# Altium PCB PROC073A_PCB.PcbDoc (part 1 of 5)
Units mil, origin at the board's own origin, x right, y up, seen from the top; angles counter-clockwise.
Board outline 2165.35 x 2165.35 mil, 6 copper layers (Top Layer, L2, L3, L4, L5, Bottom Layer), stack 55.77 mil thick; 284 components, 233 nets, 945 pads, 1419 vias.
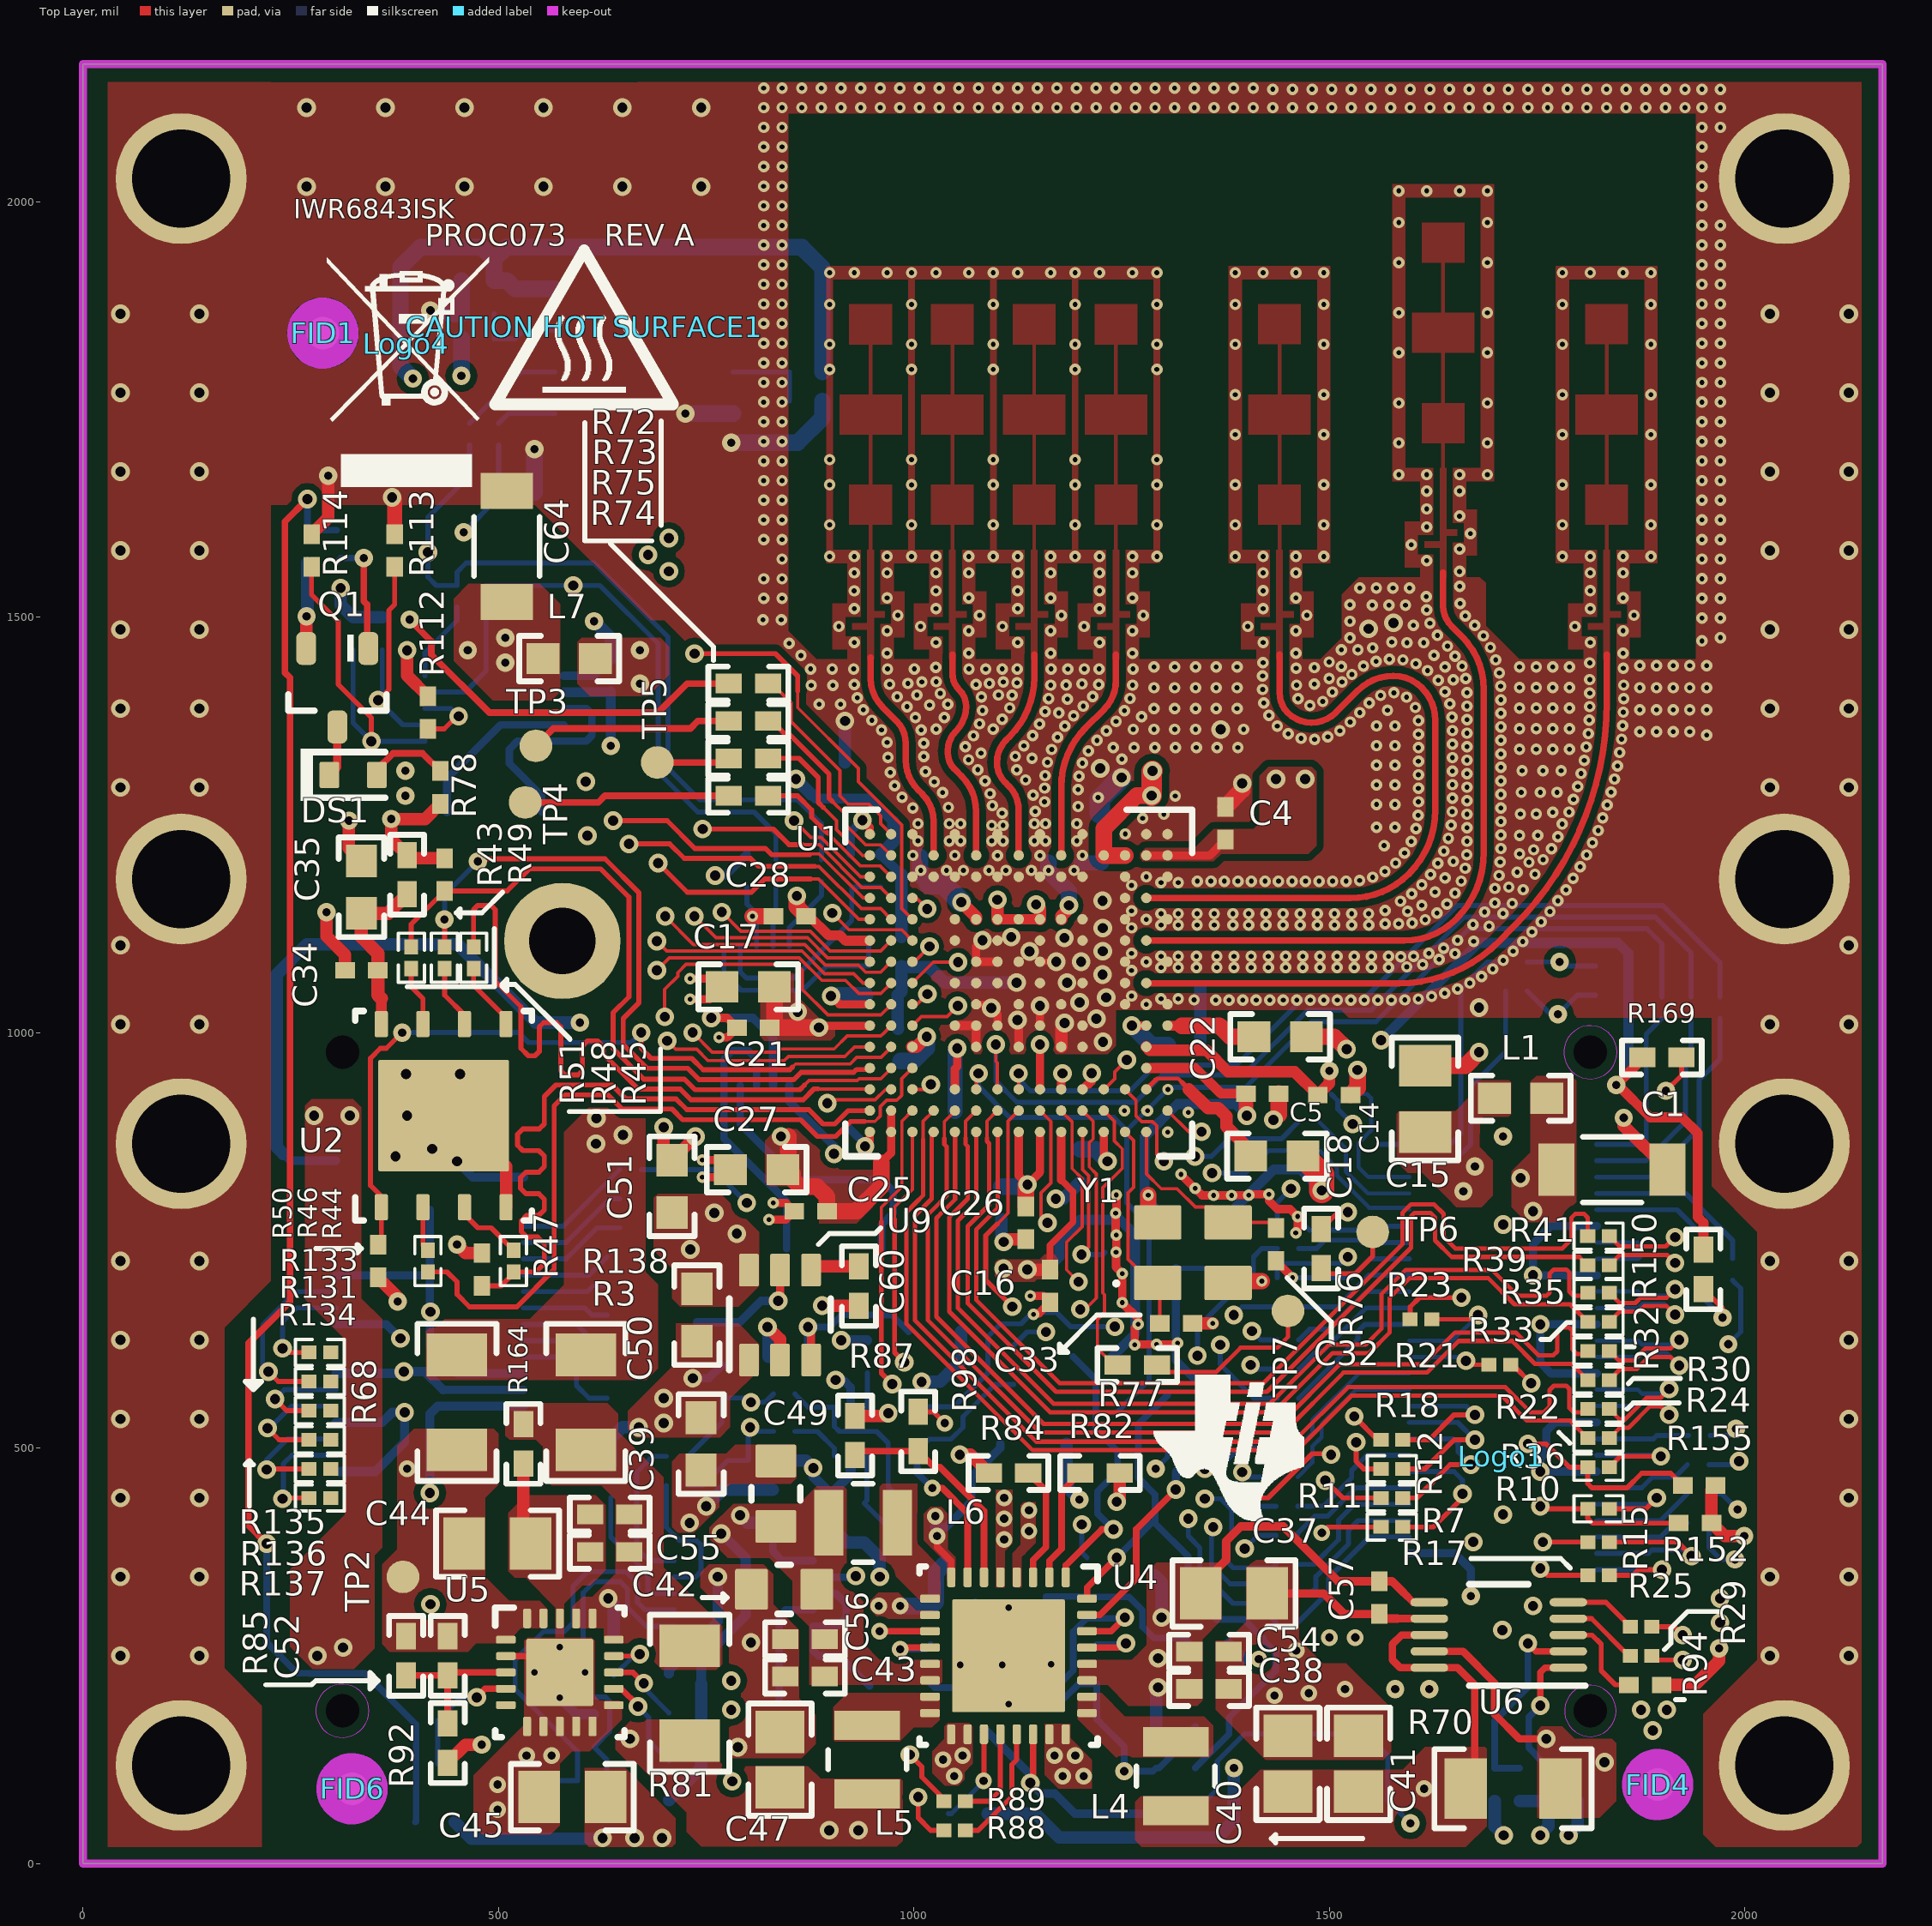
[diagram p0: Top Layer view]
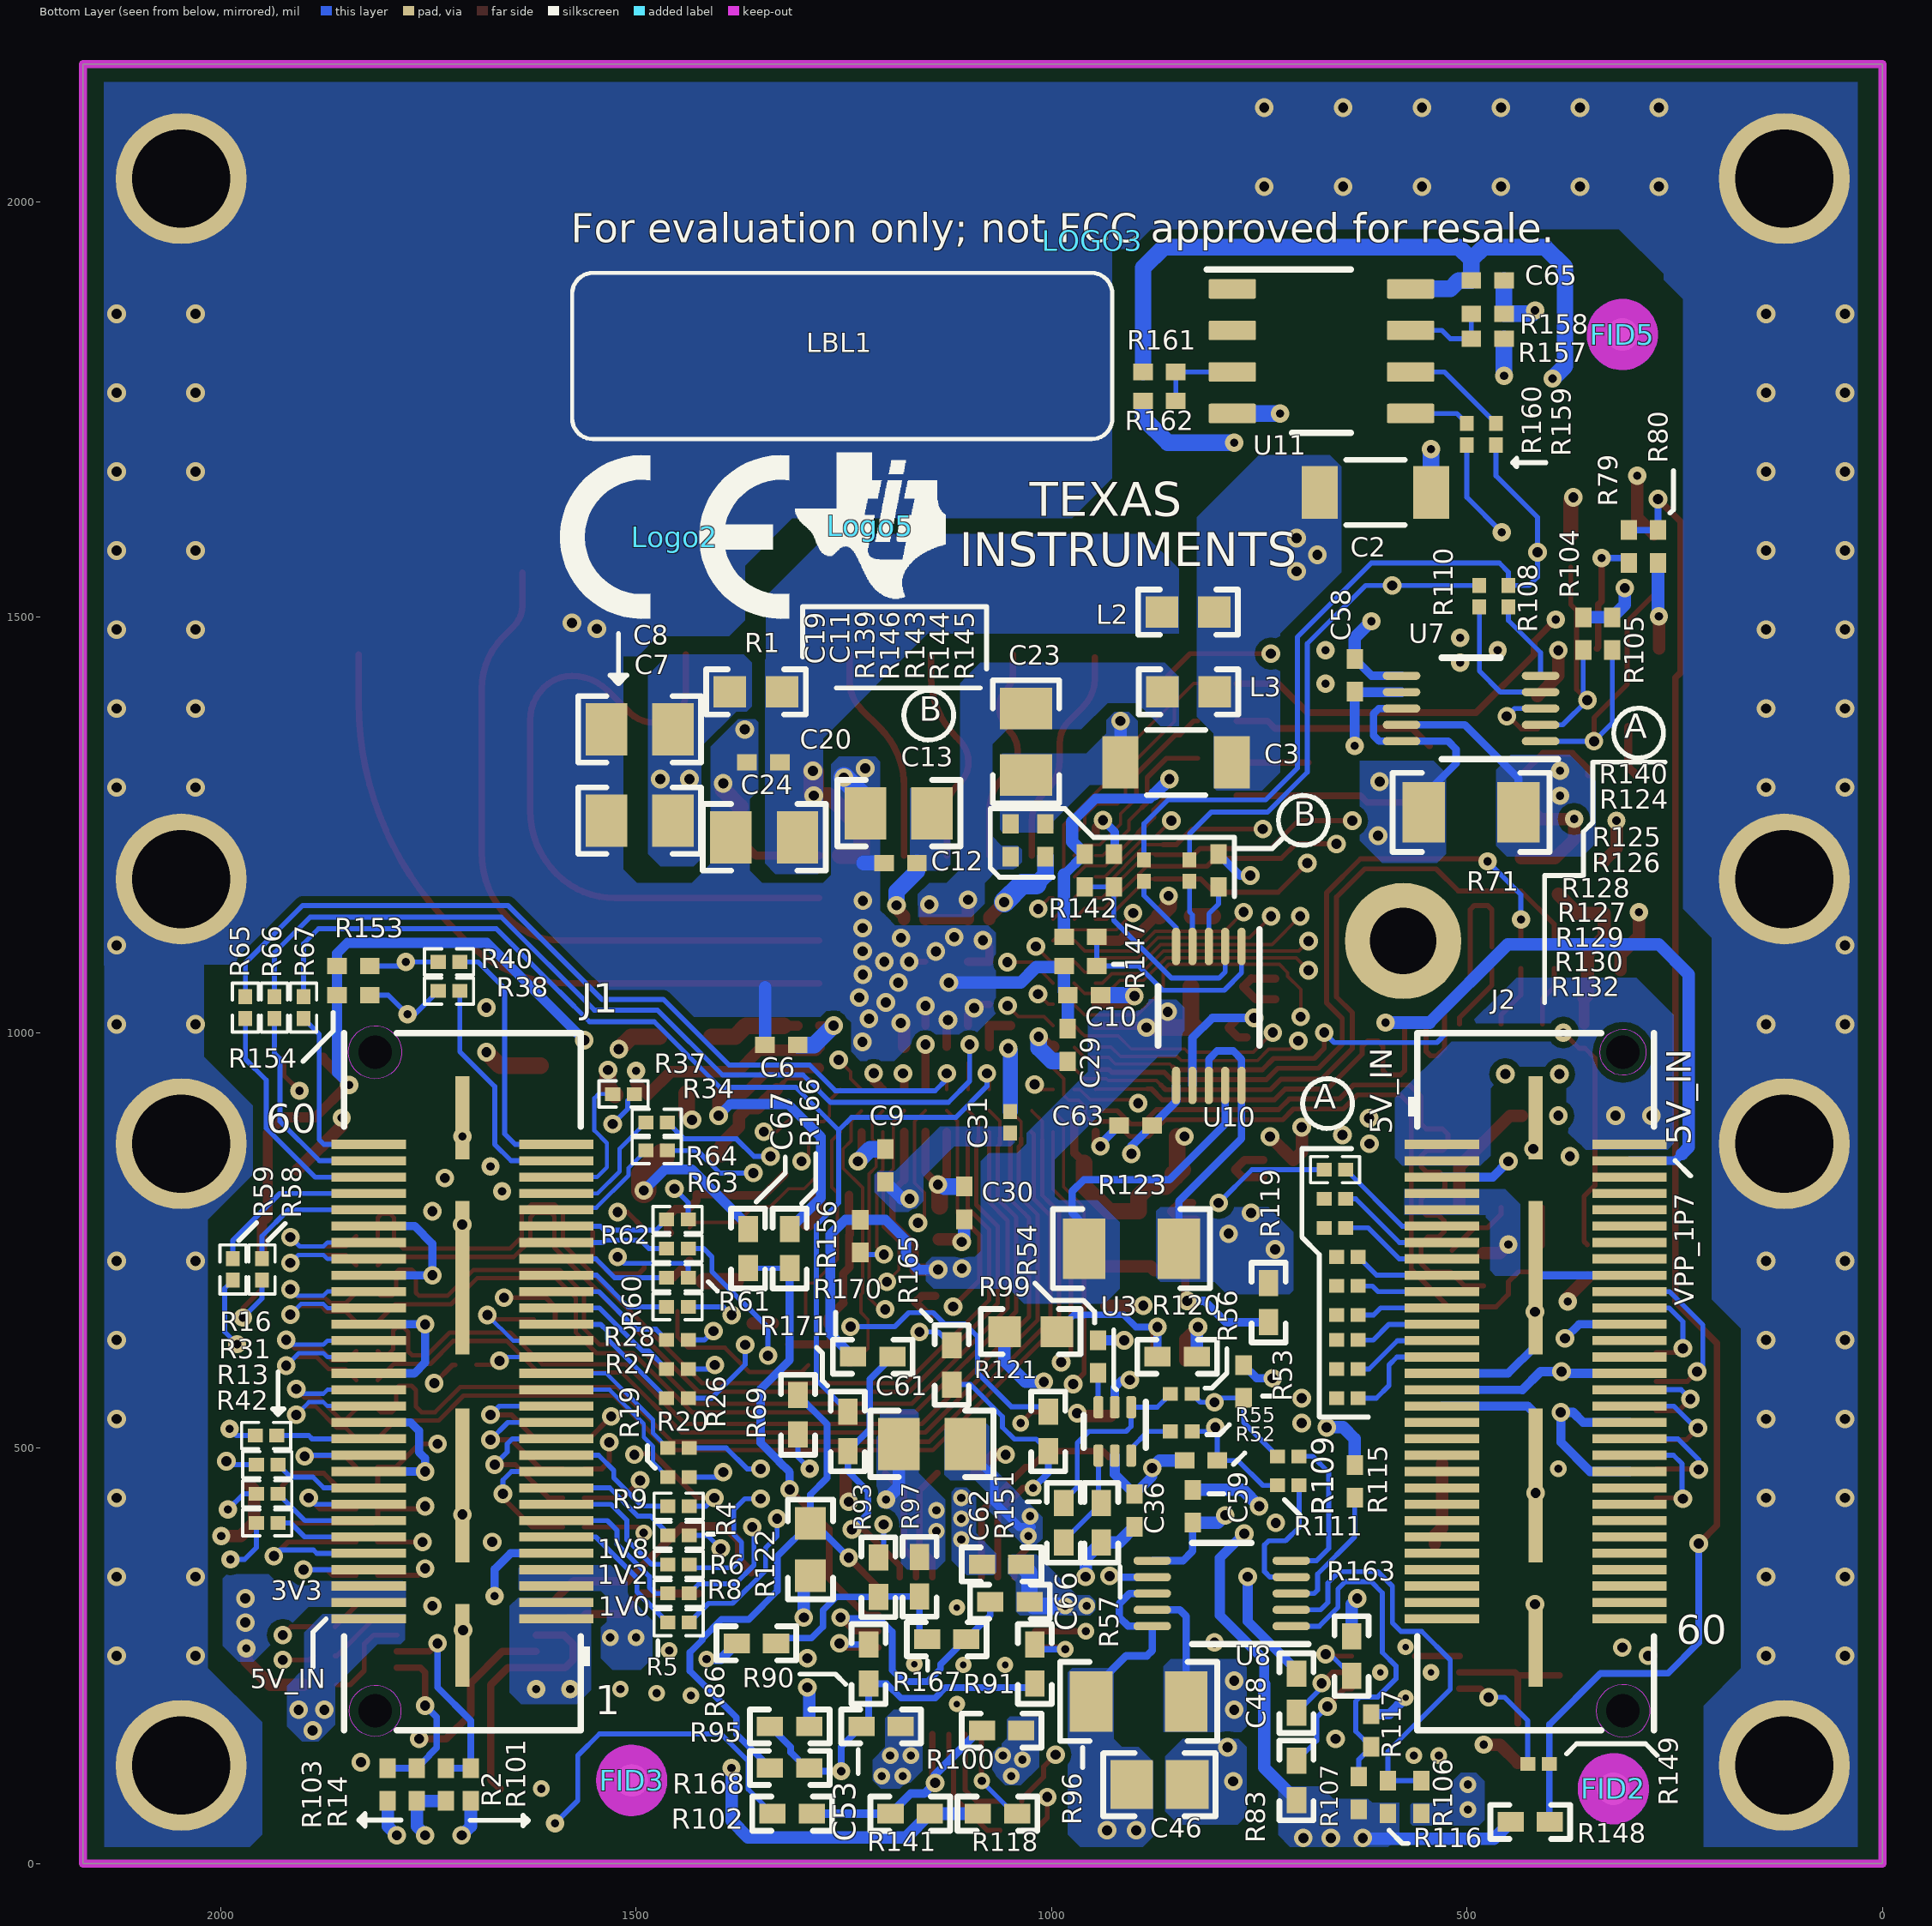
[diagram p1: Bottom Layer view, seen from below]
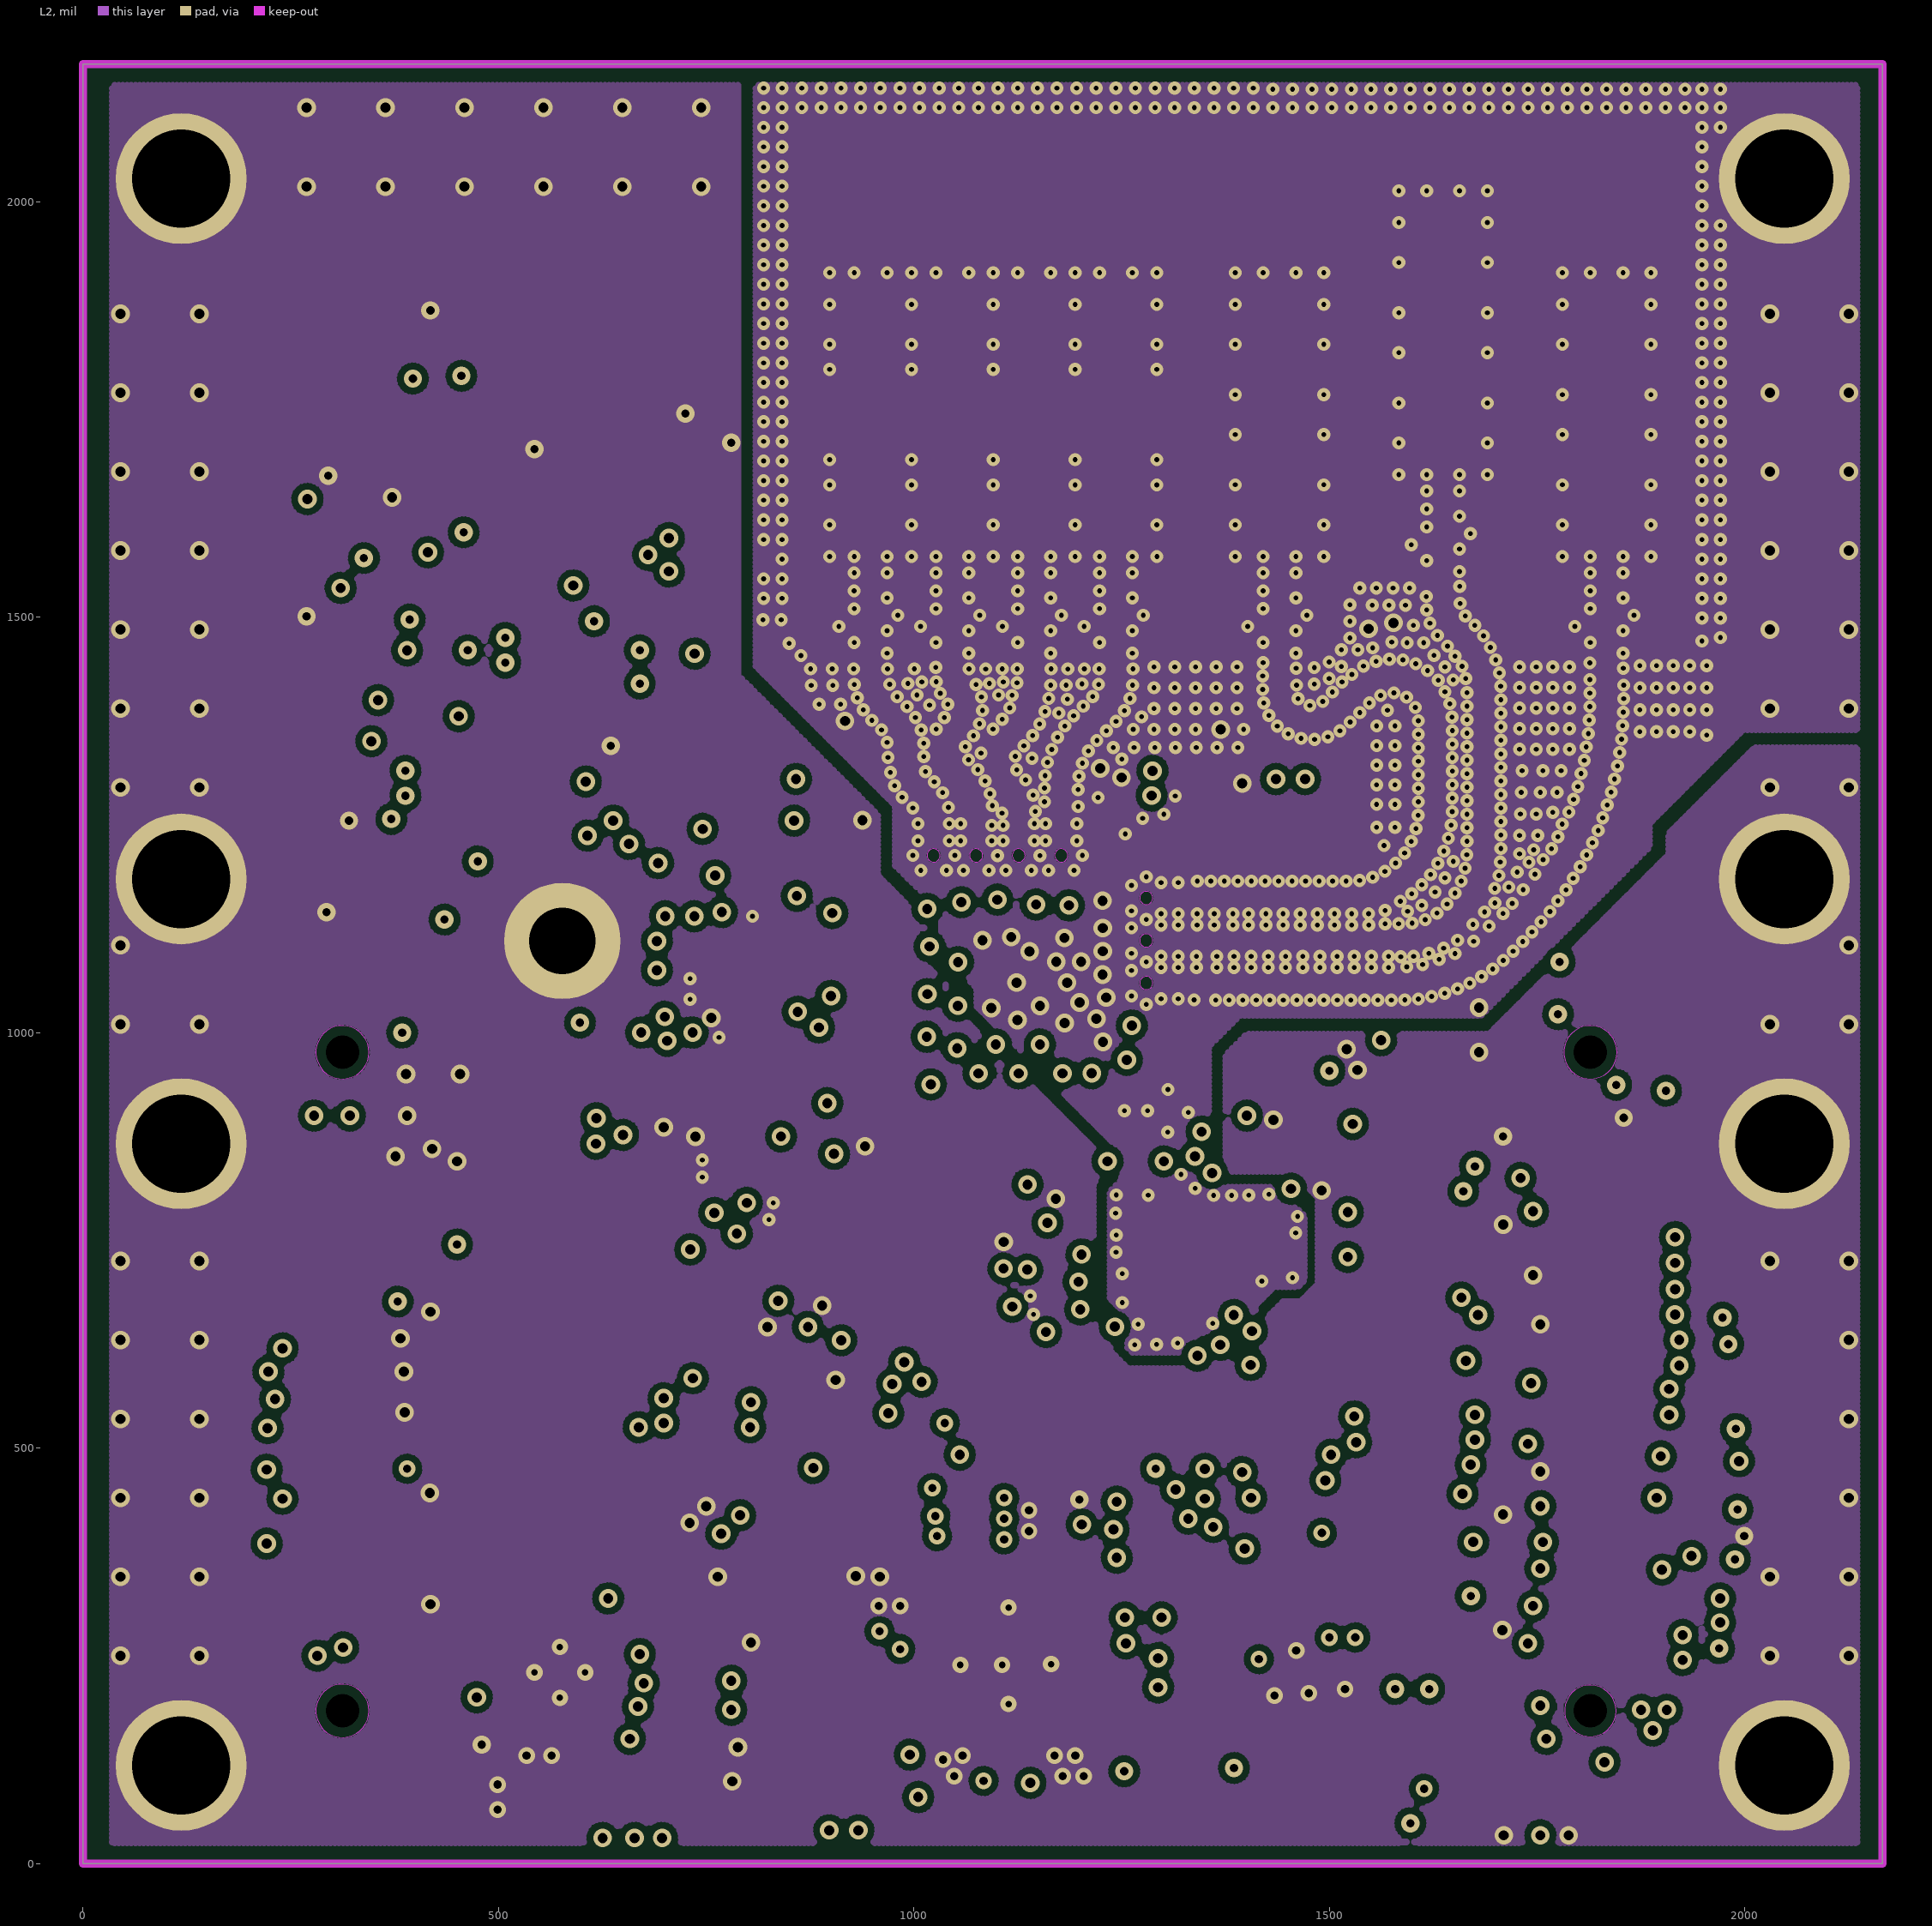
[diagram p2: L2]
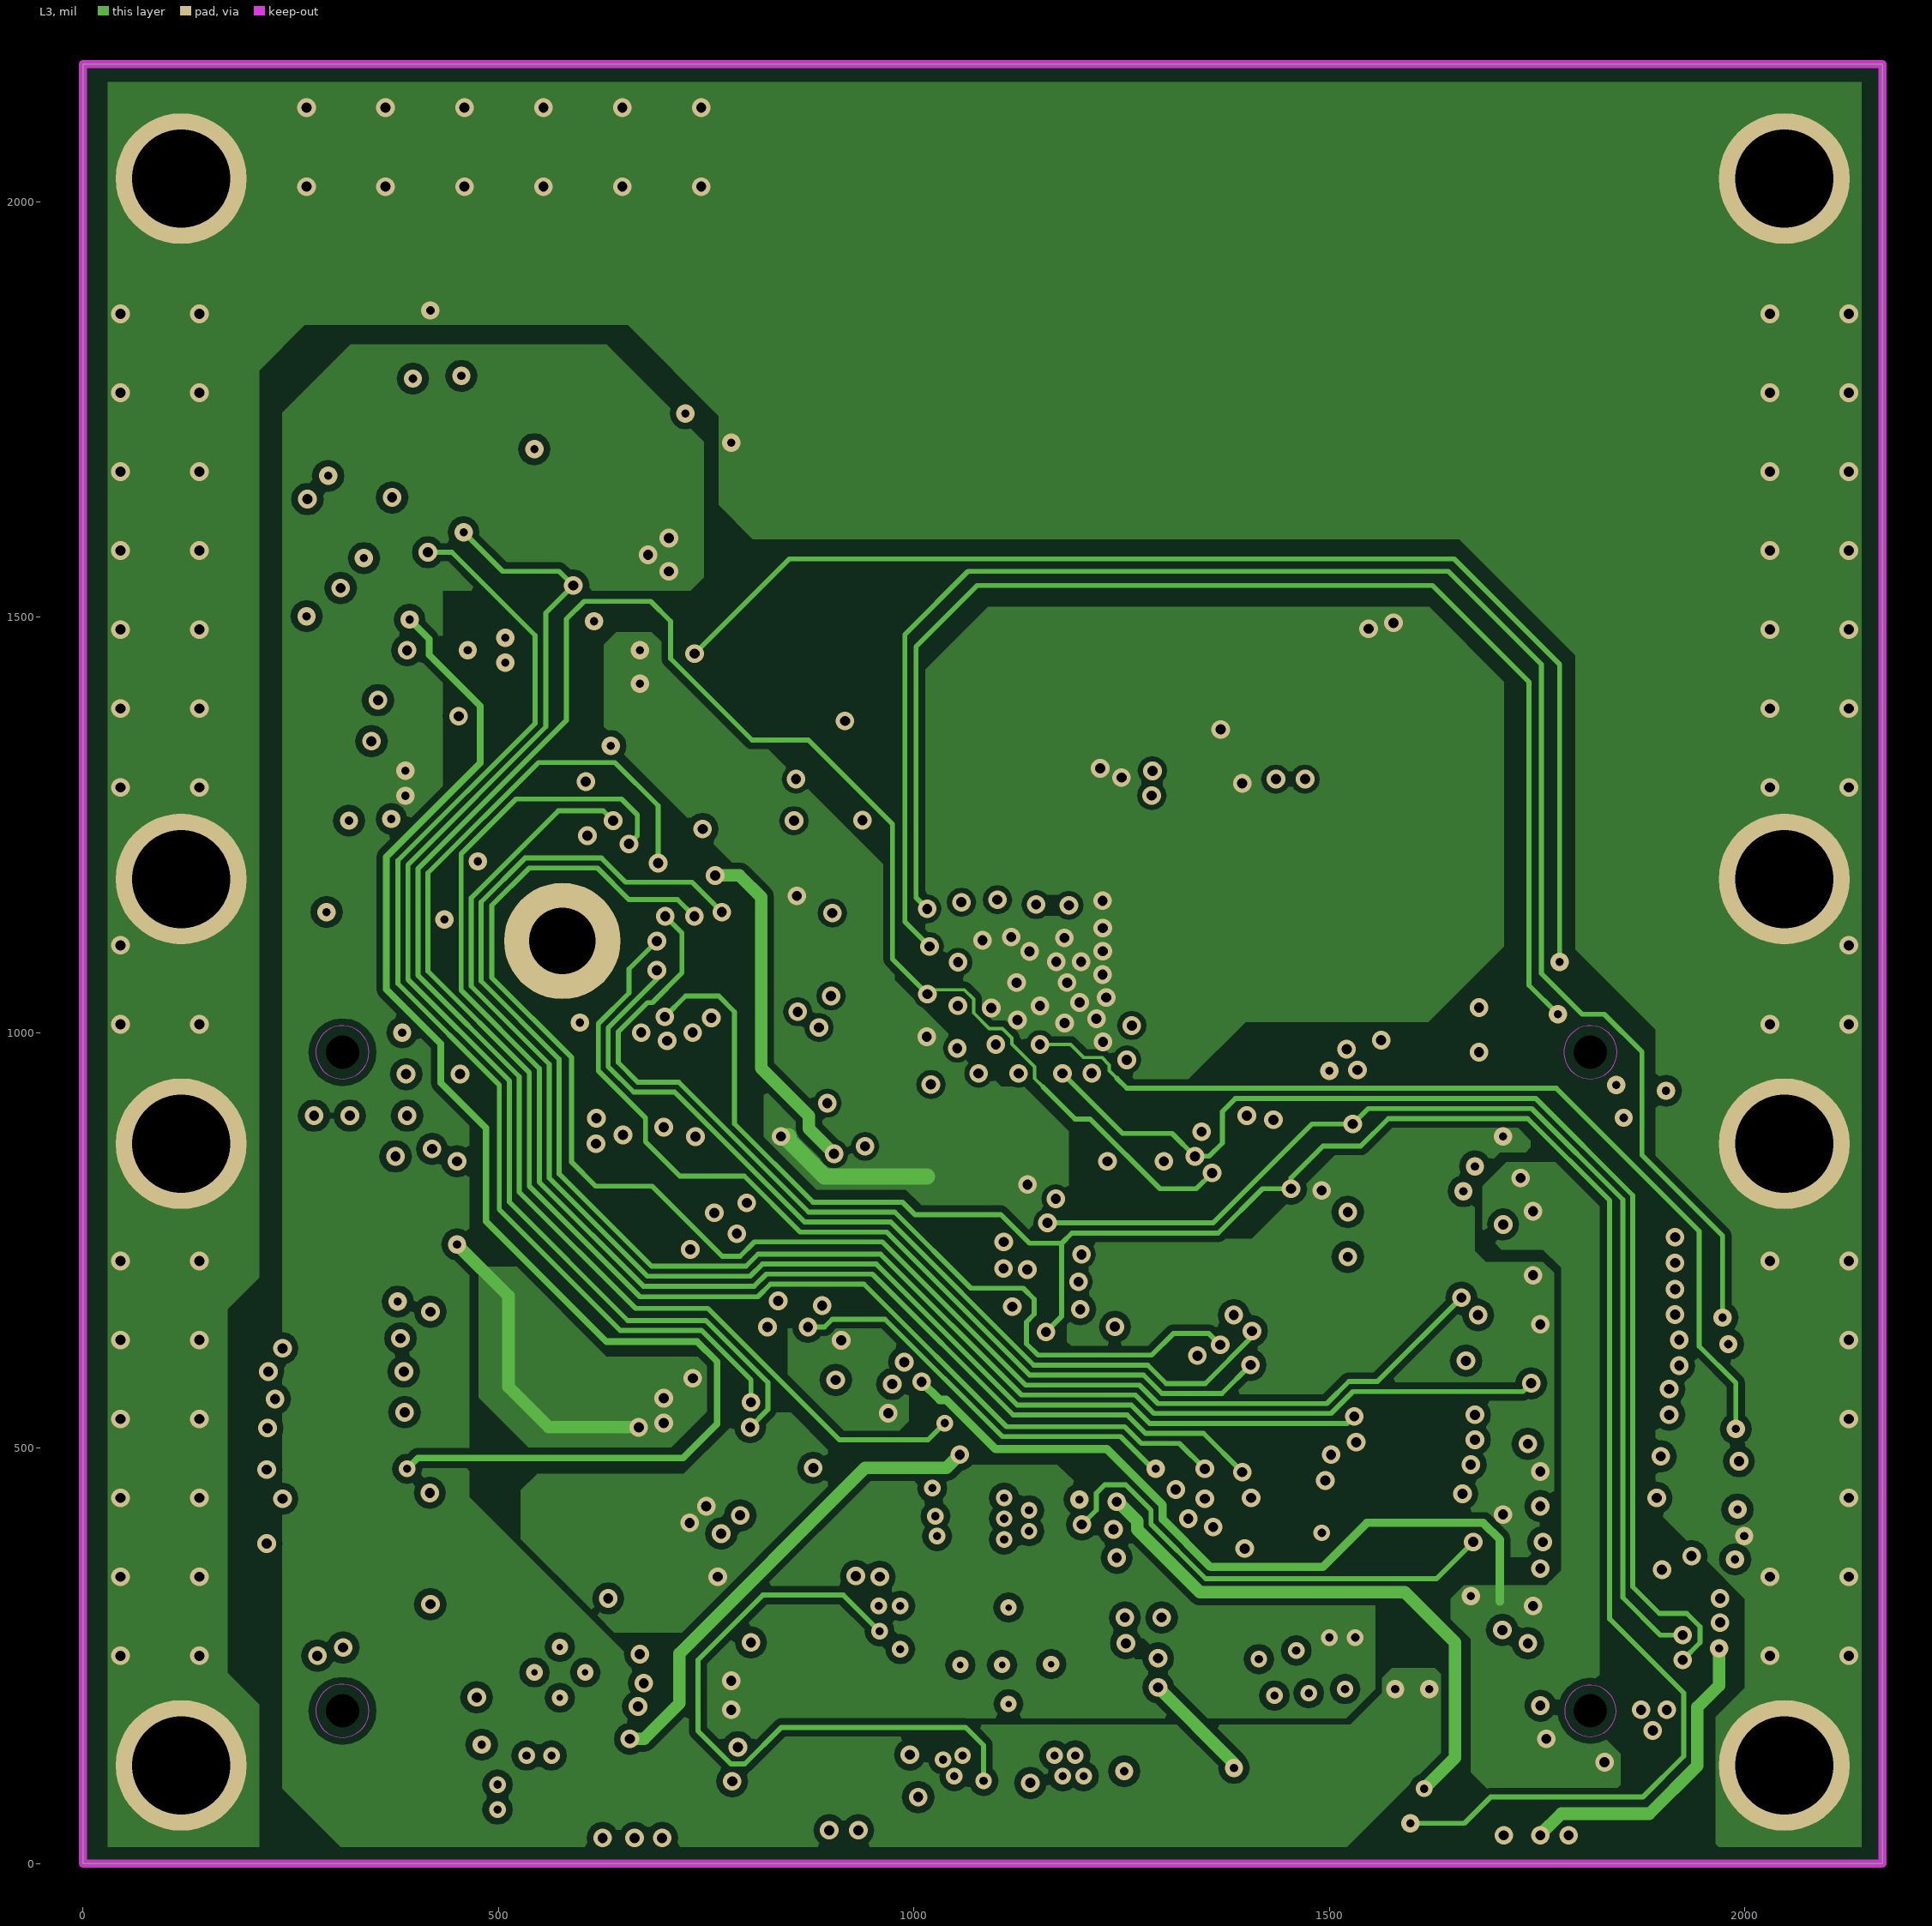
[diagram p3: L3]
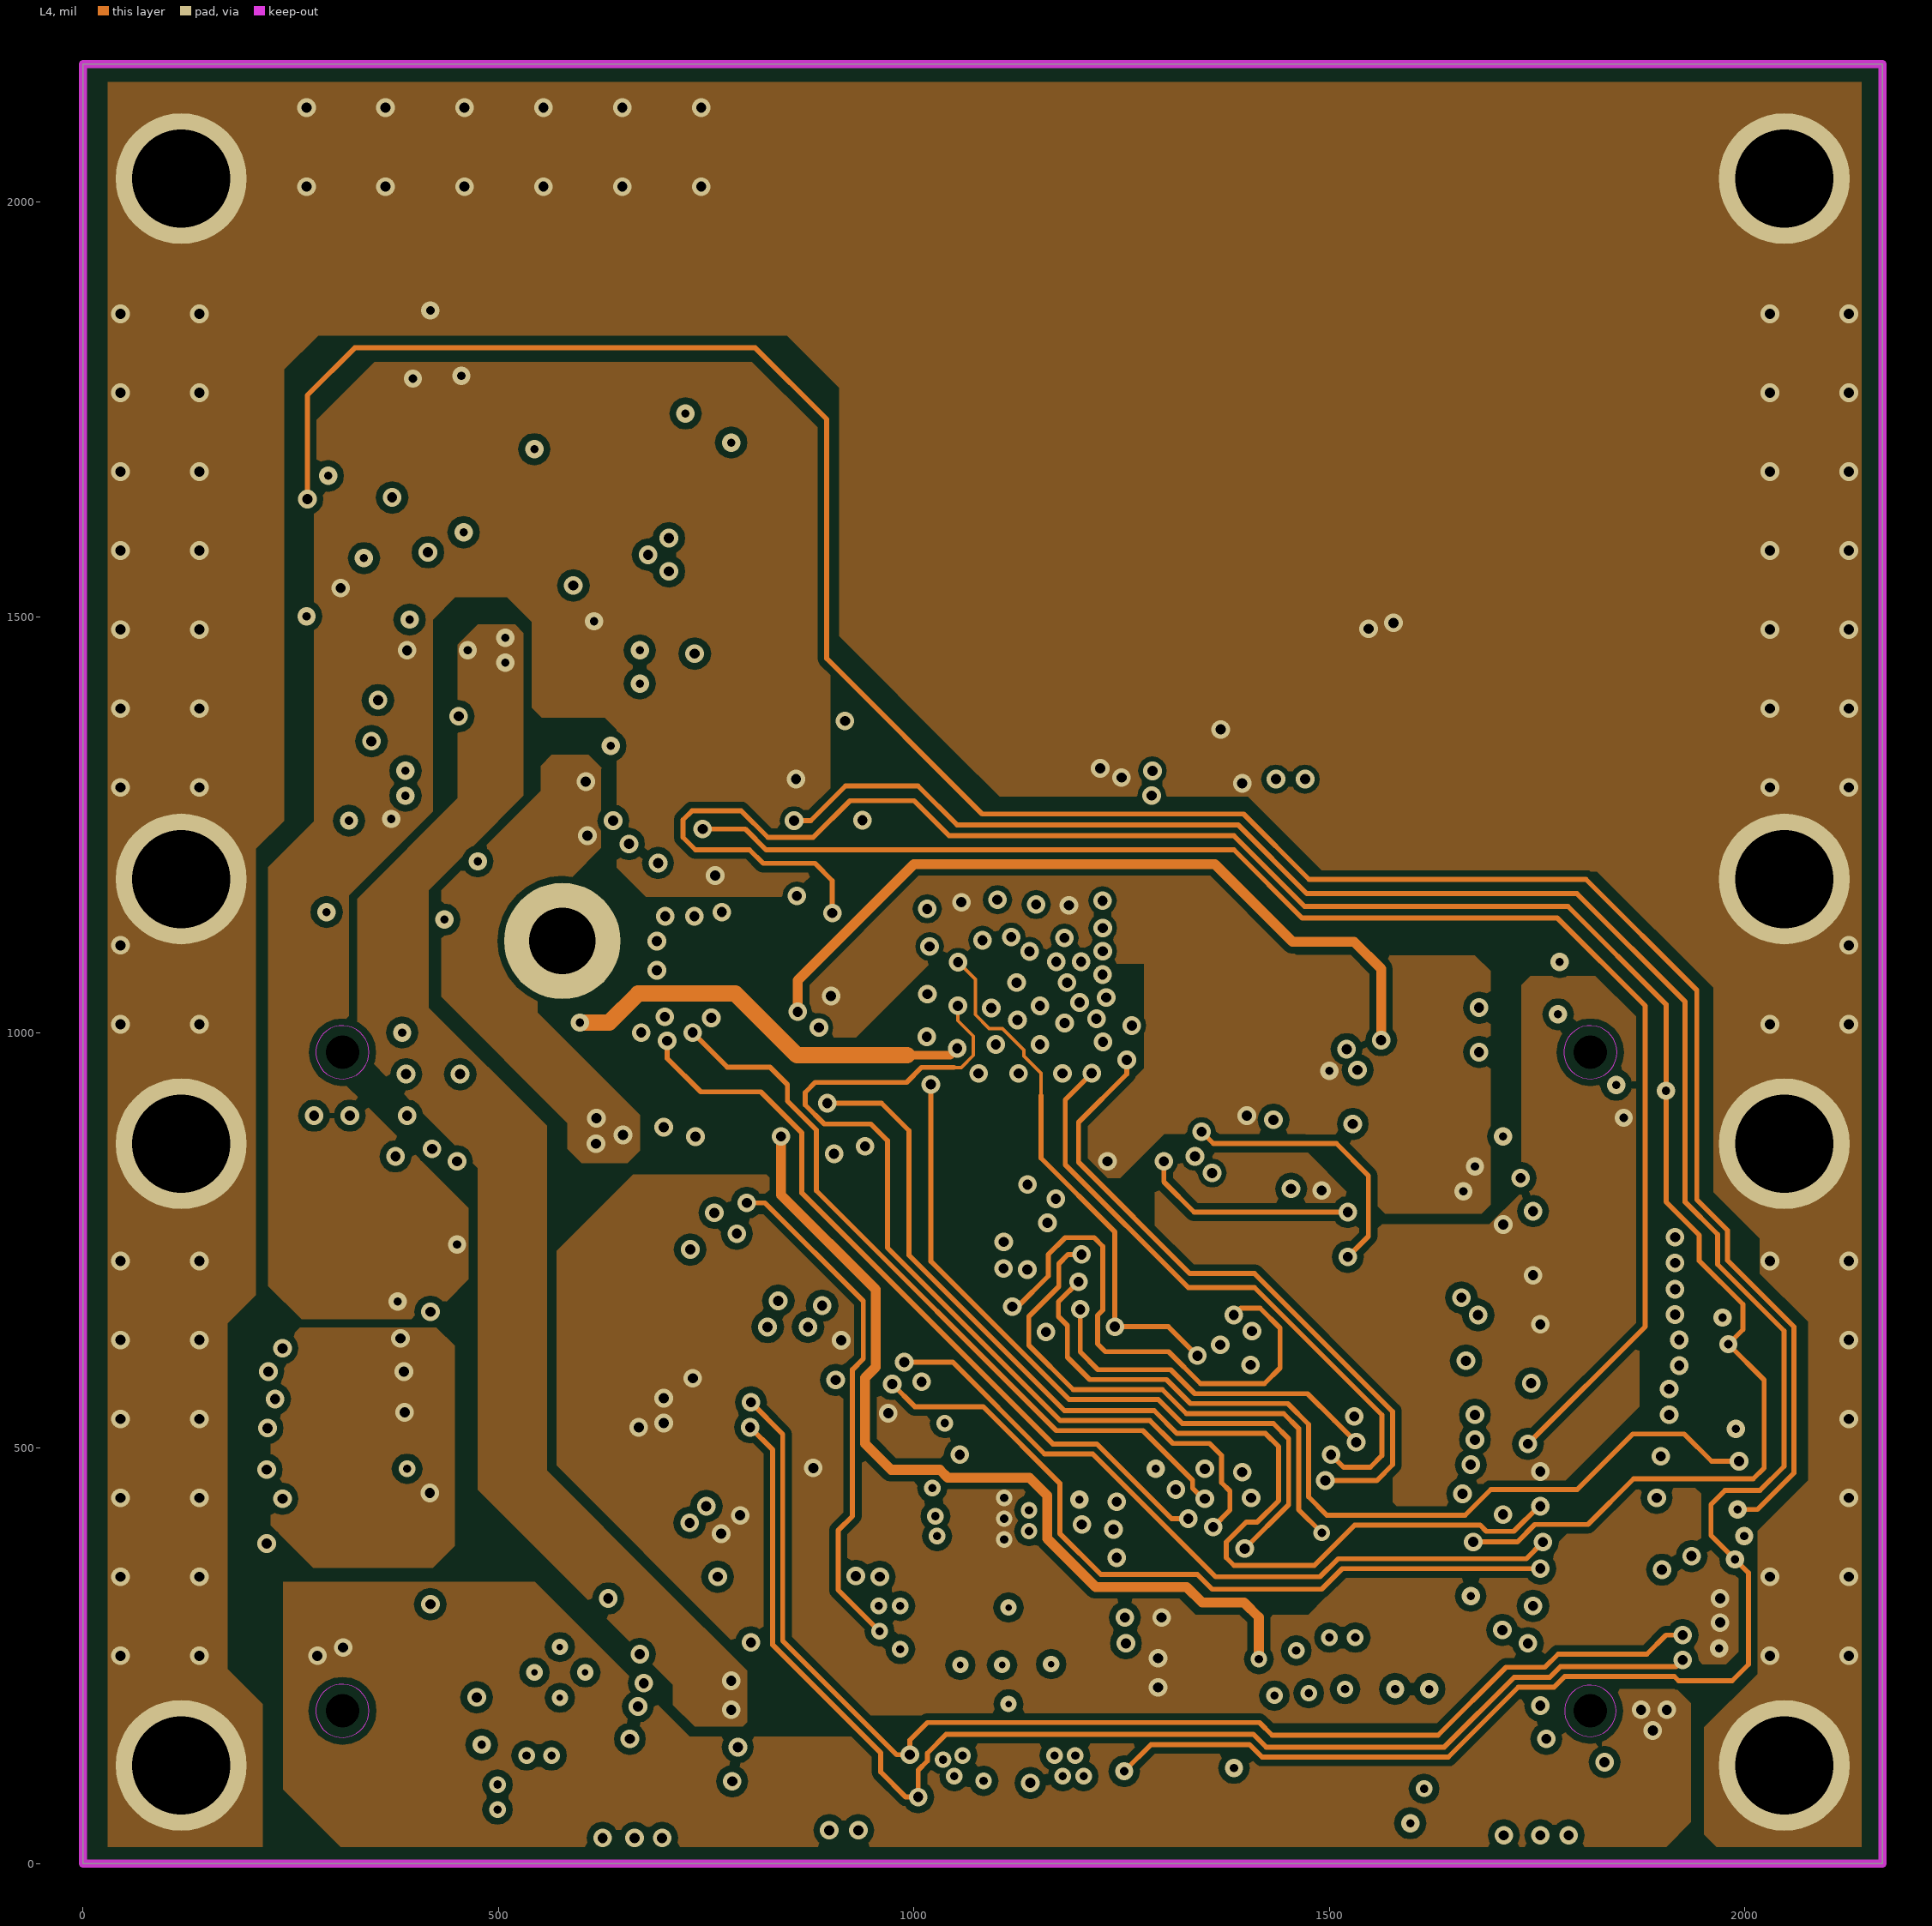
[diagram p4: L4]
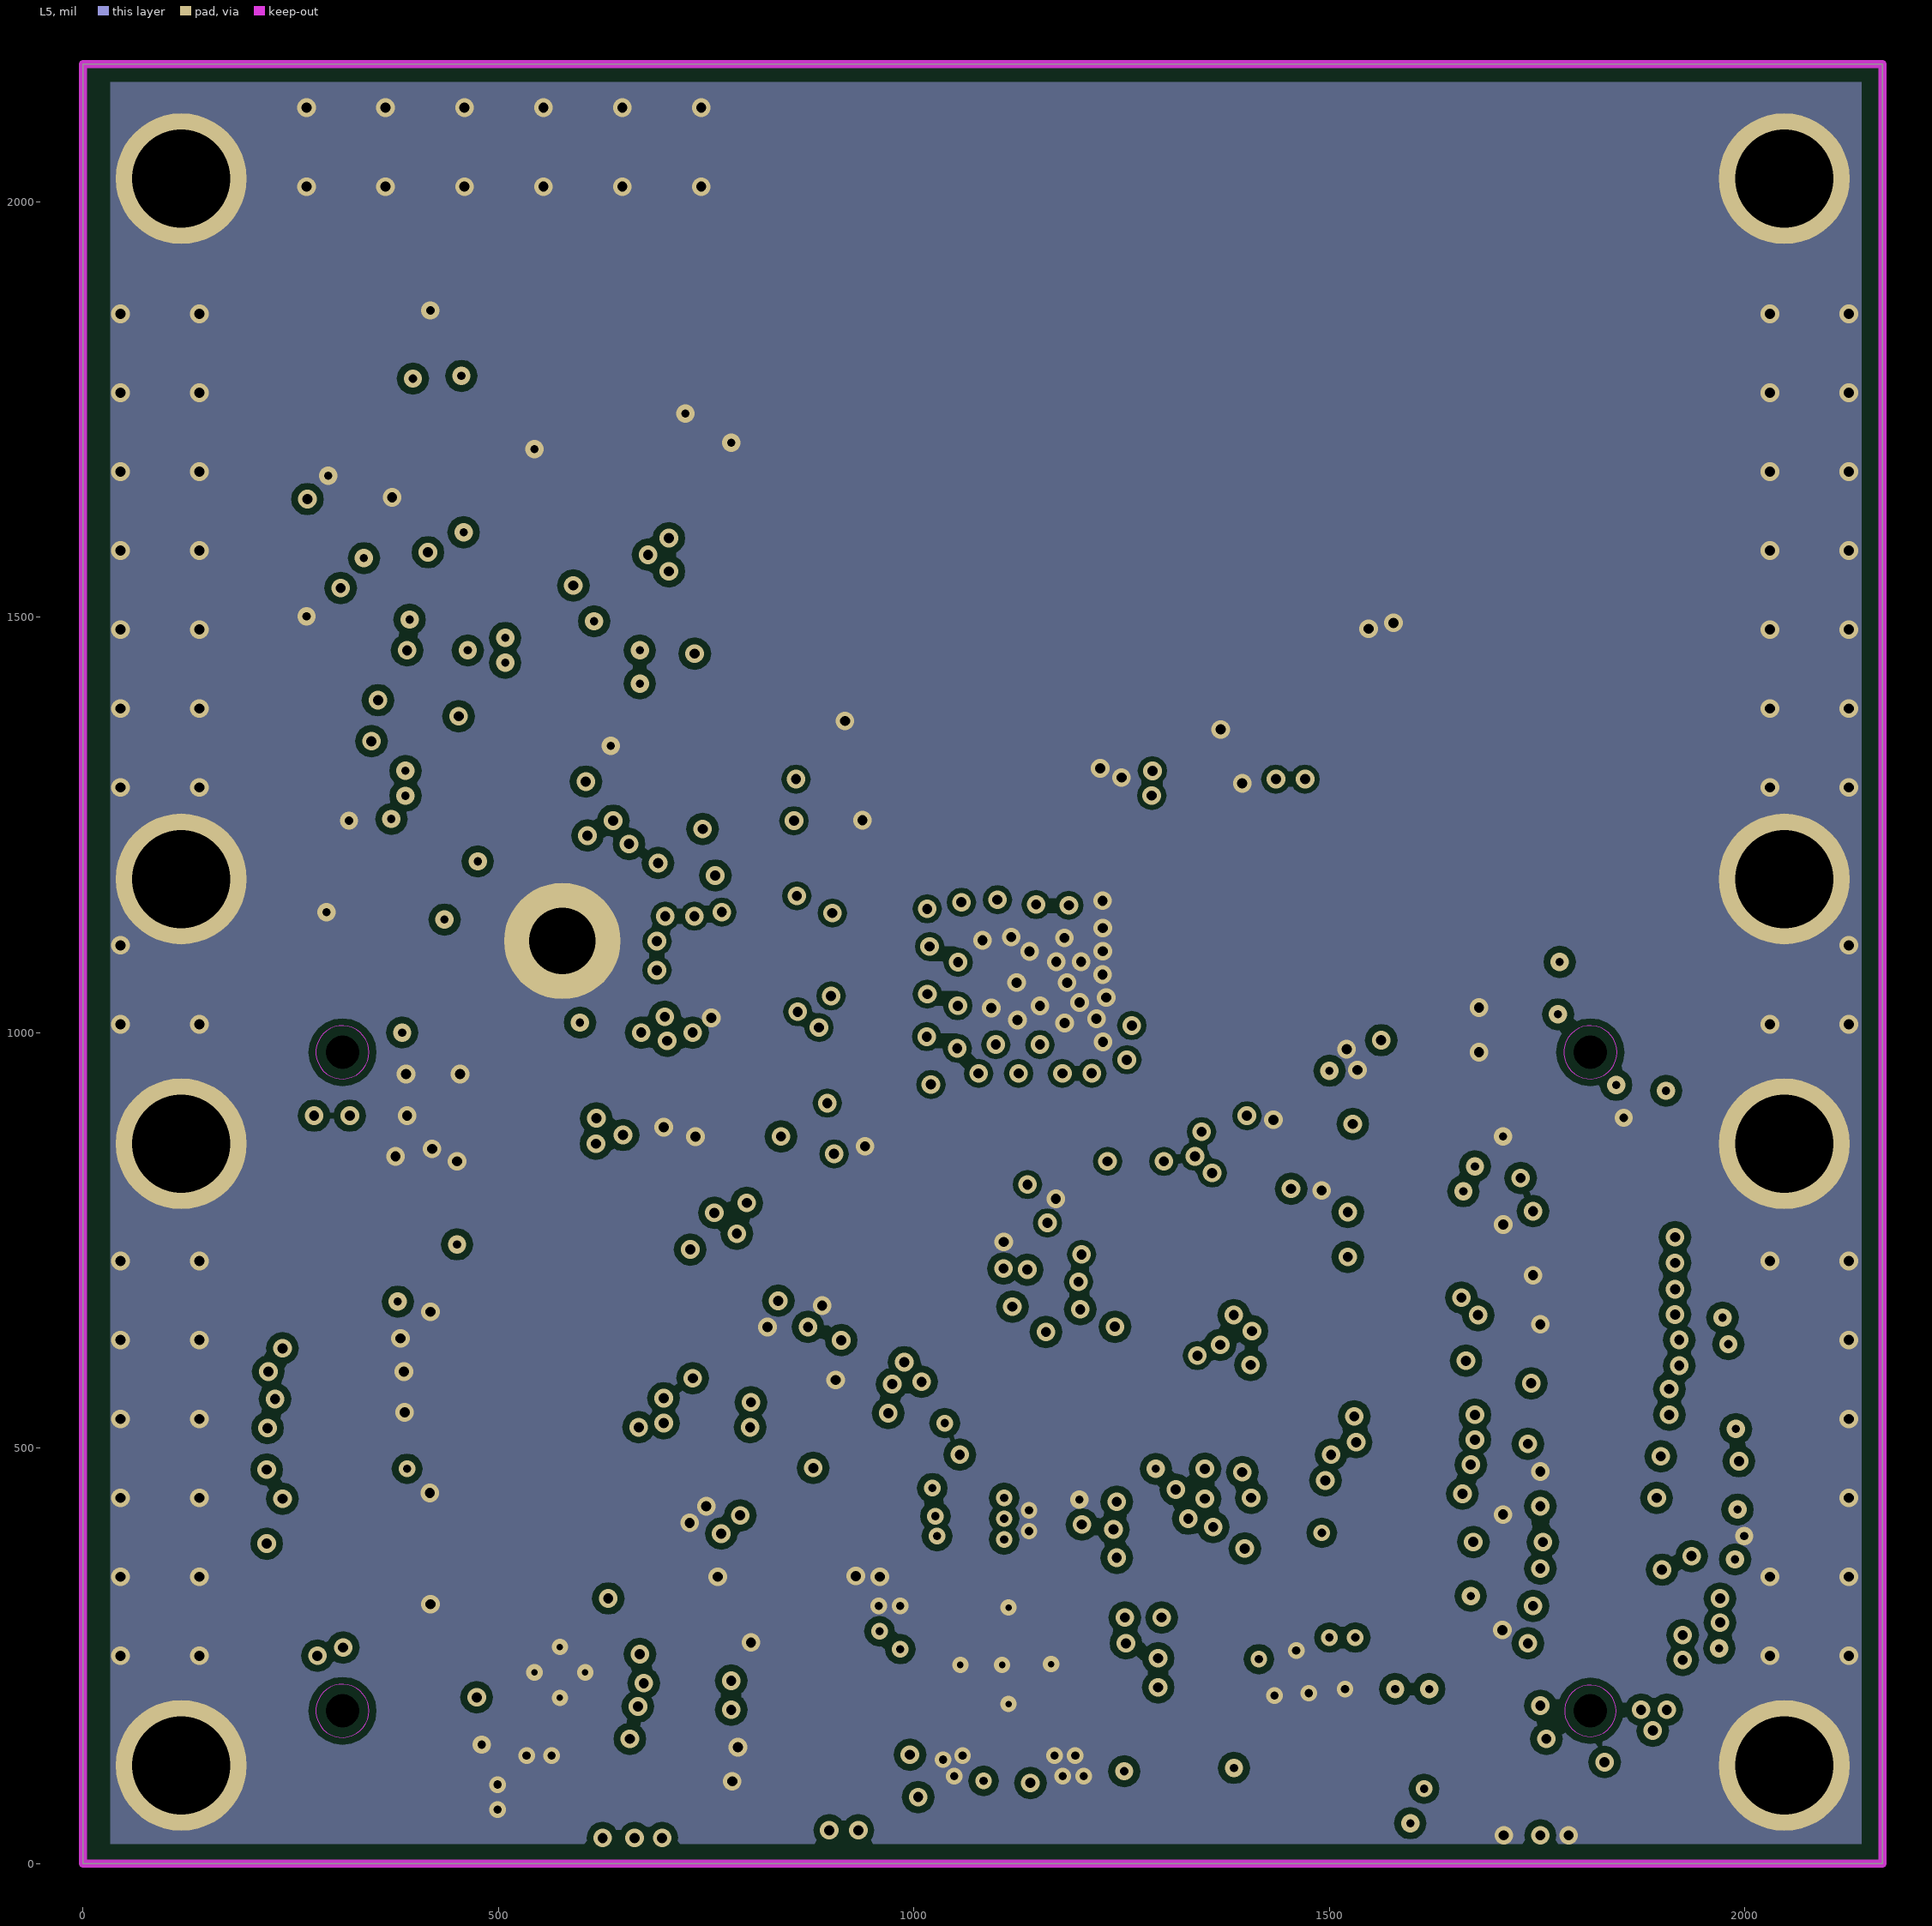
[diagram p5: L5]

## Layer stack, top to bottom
Top Solder: solder mask 0.8, Solder Resist, Dk 1
Top Layer: signal copper 1.6
Dielectric 1: dielectric 4, RO4835 LOPRO, Dk 3.66
L2: signal copper 1.4
Dielectric 2: dielectric 5.67, 1080 (66)X2  370HR, Dk 3.9
L3: signal copper 1.2
Dielectric 3: dielectric 28, 4-7628  370HR, Dk 4.36
L4: signal copper 1.2
Dielectric 4: dielectric 5.9, 1080 (66)X2  370HR, Dk 3.9
L5: signal copper 1.2
Dielectric 5: core 4, 1-2166   370HR, Dk 4.26
Bottom Layer: signal copper 1.6
Bottom Solder: solder mask 0.8, Solder Resist, Dk 1

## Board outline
0,0 2165.35,0 2165.35,2165.35 0,2165.35

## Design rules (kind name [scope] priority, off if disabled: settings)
AcuteAngle [All] p1: minimum=4.50000000000000E+0001 checktracksonly=FALSE
AssemblyTestPointUsage [All] p1: valid=2
Clearance "Clr_L2_GND Cut out (400 Mircrons)" [OnLayer('L2') and InPolygon vs IsKeepOut] p1: gap=0 ignorepadtopadclearanceinfootprint=FALSE except(7: Arc-Arc Arc-Track)
Clearance "Clr_L1_GND Cut Out (800 Mirons)_1" [OnLayer('L2')] p2: gap=6 ignorepadtopadclearanceinfootprint=FALSE except(0: Arc-Hole Track-Hole SMDPad-Hole THPad-Hole Via-Hole Fill-Hole Poly-Hole Region-Hole Text-Hole; 8: Arc-Fill Arc-Poly Arc-Region Track-Fill Track-Poly Track-Region SMDPad-Fill SMDPad-Poly SMDPad-Region THPad-Fill THPad-Poly THPad-Region Via-Fill Via-Poly Via-Region Fill-Fill Fill-Poly Fill-Region Poly-Poly Poly-Region Region-Region)
Clearance Clearance_Fid [IsKeepOut and InComponentClass('FiducialMark') vs IsPad and InComponentClass('FiducialMark')] p3: gap=0 ignorepadtopadclearanceinfootprint=FALSE
Clearance "Clearance_Diff Pairs_LVDS" [InNetClass('Diff Pairs') vs InNetClass('Diff Pairs')] p4: gap=6 ignorepadtopadclearanceinfootprint=FALSE except(0: Arc-Hole Track-Hole SMDPad-Hole THPad-Hole Via-Hole Fill-Hole Poly-Hole Region-Hole Text-Hole; 4: Arc-SMDPad Arc-THPad Arc-Via Track-SMDPad Track-THPad Track-Via; 5: Arc-Arc Arc-Track Track-Track; 8: Arc-Fill Arc-Poly Arc-Region Track-Fill Track-Poly Track-Region Via-Fill Via-Poly Via-Region Fill-Fill Fill-Poly Fill-Region Poly-Poly Poly-Region Region-Region)
Clearance "Clr_L1_GND Cut Out (800 Mirons)" [OnTopLayer and InPoly vs IsKeepOut] p5: gap=0 ignorepadtopadclearanceinfootprint=FALSE
Clearance "Clearance_TX and RX" [InNetClass('TX and RX')] p6: gap=8 ignorepadtopadclearanceinfootprint=FALSE except(0: Arc-Hole Track-Hole SMDPad-Hole THPad-Hole Via-Hole Fill-Hole Poly-Hole Region-Hole Text-Hole; 4: Arc-Text Track-Text SMDPad-Text THPad-Text Via-Text Fill-Text Poly-Text Region-Text Text-Text; 7.7: Fill-Fill Fill-Poly Fill-Region Poly-Poly Poly-Region Region-Region; 7.9: Arc-Via Track-Via; 10: Arc-SMDPad Arc-THPad Track-SMDPad Track-THPad SMDPad-SMDPad SMDPad-THPad SMDPad-Via THPad-THPad THPad-Via)
Clearance Clearance_BGA [WithinRoom('BGA1')] p7: gap=4 ignorepadtopadclearanceinfootprint=FALSE except(0: Arc-Hole Track-Hole SMDPad-Hole THPad-Hole Via-Hole Fill-Hole Poly-Hole Region-Hole Text-Hole; 6: SMDPad-Poly THPad-Poly Via-Poly; 7.5: Region-Region; 7.87: Arc-Text Track-Text SMDPad-Text THPad-Text Via-Text Fill-Text Poly-Text Region-Text Text-Text; 8: Arc-Poly Track-THPad Track-Poly THPad-THPad Fill-Poly Poly-Poly)
Clearance [All] p8: gap=6 ignorepadtopadclearanceinfootprint=FALSE except(0: Arc-Hole Track-Hole SMDPad-Hole THPad-Hole Via-Hole Fill-Hole Poly-Hole Region-Hole Text-Hole; 8: Arc-Fill Arc-Poly Arc-Region Track-Fill Track-Poly Track-Region SMDPad-Fill SMDPad-Poly SMDPad-Region THPad-Fill THPad-Poly THPad-Region Via-Fill Via-Poly Via-Region Fill-Fill Fill-Poly Fill-Region Poly-Poly Poly-Region Region-Region)
ComponentClearance "ComponentClearance_WEE Logo" [InComponent('Logo4')] p1: gap=0 collisioncheckmode=3 verticalgap=0 showdistances=TRUE
ComponentClearance Comp_Clr-R158_R157 [InComponent('R157') vs InComponent('R158')] p2: gap=0 collisioncheckmode=3 verticalgap=0 showdistances=TRUE
ComponentClearance Comp_Clr-R101_R2 [InComponent('R2') vs InComponent('R101')] p3: gap=0 collisioncheckmode=3 verticalgap=0 showdistances=TRUE
ComponentClearance Comp_Clr-C42_L6 [InComponent('C42') vs InComponent('L6')] p4: gap=0 collisioncheckmode=3 verticalgap=0 showdistances=TRUE
ComponentClearance ComponentClearance_R77 [InComponent('R77') vs InComponent('Logo1')] p5: gap=0 collisioncheckmode=3 verticalgap=0 showdistances=TRUE
ComponentClearance ComponentClearance_Logo [InComponentClass('Logo')] p6: gap=0 collisioncheckmode=3 verticalgap=0 showdistances=TRUE
ComponentClearance "ComponentClearance_Mounting Holes_Fiducial Marks" [InComponentClass('FiducialMark') vs InPadClass('Mounting Holes PADS')] p7: gap=50 collisioncheckmode=3 verticalgap=10 showdistances=TRUE
ComponentClearance [All] p8: gap=10 collisioncheckmode=3 verticalgap=10 showdistances=TRUE
DiffPairsRouting [All] p1: maxlimit=5 minlimit=4 mostfreqgap=5 toplayer_minwidth=4 toplayer_maxwidth=5.2 toplayer_prefwidth=5.2 midlayer1_minwidth=4 midlayer1_maxwidth=5.2 midlayer1_prefwidth=5.2 midlayer2_minwidth=4 midlayer2_maxwidth=5.2 midlayer2_prefwidth=5.2 midlayer3_minwidth=4 midlayer3_maxwidth=5.2 midlayer3_prefwidth=5.2 midlayer4_minwidth=4 midlayer4_maxwidth=5.2 midlayer4_prefwidth=5.2 bottomlayer_minwidth=4 bottomlayer_maxwidth=5.2 bottomlayer_prefwidth=5.2 maxuncoupledlength=500
FabricationTestPointUsage TestPointUsage [All] p1: valid=2 allowmultiple=FALSE
FabricationTestpoint Testpoint [All] p1: side=3 testpointundercomponent=TRUE minsize=40 maxsize=100 preferedsize=60 minholesize=0 maxholesize=40 preferedholesize=32 testpointgrid=1 allowsidetop=TRUE allowsidebottom=TRUE usegrid=TRUE gridtolerance=0.01
FanoutControl Fanout_LCC [IsLCC] p1: bgadir=Out bgaviamode=Centered fanoutstyle=Auto fanoutdirection=Alternating viagrid=1 // Fanout_LCC (Default Rule)
FanoutControl Fanout_BGA [IsBGA] p2: bgadir=Out bgaviamode=Centered fanoutstyle=Auto fanoutdirection=Alternating viagrid=1 // Fanout_BGA (Default Rule)
FanoutControl Fanout_Default [All] p4: bgadir=Out bgaviamode=Centered fanoutstyle=Auto fanoutdirection=Alternating viagrid=1 // Fanout_Default (Default Rule)
FanoutControl Fanout_Small [(CompPinCount < 5)] p5: bgadir=Out bgaviamode=Centered fanoutstyle=Auto fanoutdirection=OutThenIn viagrid=1 // Fanout_Small (Default Rule)
Height Room_Hieght [WithinRoom('Room_Hieght 1 MM')] p1: minheight=0 maxheight=41.34 prefheight=39.37
HoleSize [All] p1: absolutevalues=TRUE maxlimit=280 minlimit=5.9 maxpercent=80.000 minpercent=20.000
HoleToHoleClearance HoleToHoleClearance_1 [InDrillLayerPair('Top Layer - L2') vs InDrillLayerPair('Top Layer - L2')] p1: gap=7.7 allowstackedmicrovias=TRUE
HoleToHoleClearance [All] p2: gap=8 allowstackedmicrovias=TRUE
Length Length_Flash [InNetClass('Flash')] p1: maxlimit=1026 minlimit=826
MatchedLengths DiffPair_MatchedLengths [InDifferentialPair ('NewDifferentialPair3')] p1: tolerance=5 checknetsindiffpair=TRUE checkdiffpairvsdiffpair=FALSE checkxsignals=FALSE checkothers=FALSE
MatchedLengths DiffPair_MatchedLengths_1 [InDifferentialPair ('NewDifferentialPair2')] p2: tolerance=5 checknetsindiffpair=TRUE checkdiffpairvsdiffpair=FALSE checkxsignals=FALSE checkothers=FALSE
MatchedLengths DiffPair_MatchedLengths_2 [InDifferentialPair ('NewDifferentialPair1')] p3: tolerance=5 checknetsindiffpair=TRUE checkdiffpairvsdiffpair=FALSE checkxsignals=FALSE checkothers=FALSE
MatchedLengths DiffPair_MatchedLengths_3 [InDifferentialPair ('NewDifferentialPair8')] p4: tolerance=5 checknetsindiffpair=TRUE checkdiffpairvsdiffpair=FALSE checkxsignals=FALSE checkothers=FALSE
MatchedLengths DiffPair_MatchedLengths_4 [InDifferentialPair ('NewDifferentialPair7')] p5: tolerance=5 checknetsindiffpair=TRUE checkdiffpairvsdiffpair=FALSE checkxsignals=FALSE checkothers=FALSE
MatchedLengths DiffPair_MatchedLengths_5 [InDifferentialPair ('NewDifferentialPair6')] p6: tolerance=5 checknetsindiffpair=TRUE checkdiffpairvsdiffpair=FALSE checkxsignals=FALSE checkothers=FALSE
MatchedLengths DiffPair_MatchedLengths_6 [InDifferentialPair ('NewDifferentialPair5')] p7: tolerance=5 checknetsindiffpair=TRUE checkdiffpairvsdiffpair=FALSE checkxsignals=FALSE checkothers=FALSE
MatchedLengths DiffPair_MatchedLengths_7 [InDifferentialPair ('NewDifferentialPair3')] p8: tolerance=5 checknetsindiffpair=TRUE checkdiffpairvsdiffpair=FALSE checkxsignals=FALSE checkothers=FALSE
MatchedLengths DiffPair_MatchedLengths_8 [InDifferentialPair ('NewDifferentialPair4')] p9: tolerance=5 checknetsindiffpair=TRUE checkdiffpairvsdiffpair=FALSE checkxsignals=FALSE checkothers=FALSE
MatchedLengths DiffPair_MatchedLengths_9 [InDifferentialPair ('NewDifferentialPair2')] p10: tolerance=5 checknetsindiffpair=TRUE checkdiffpairvsdiffpair=FALSE checkxsignals=FALSE checkothers=FALSE
MatchedLengths DiffPair_MatchedLengths_10 [InDifferentialPair ('NewDifferentialPair2')] p11: tolerance=5 checknetsindiffpair=TRUE checkdiffpairvsdiffpair=FALSE checkxsignals=FALSE checkothers=FALSE
MatchedLengths DiffPair_MatchedLengths_11 [InDifferentialPair ('NewDifferentialPair1')] p12: tolerance=5 checknetsindiffpair=TRUE checkdiffpairvsdiffpair=FALSE checkxsignals=FALSE checkothers=FALSE
MatchedLengths DiffPair_MatchedLengths_12 [InDifferentialPairClass('DIIF')] p13: tolerance=5 checknetsindiffpair=TRUE checkdiffpairvsdiffpair=FALSE checkxsignals=FALSE checkothers=FALSE
MinimumAnnularRing MinimumAnnularRing_ThermalPadVias [IsVia and InAnyComponent] p1: minimumring=3.9
MinimumAnnularRing [All] p2: minimumring=3.9
MinimumSolderMaskSliver MinimumSolderMaskSliver_Logo [InComponentClass('Logo') vs InComponentClass('Logo')] p1: minsoldermaskwidth=0.7
MinimumSolderMaskSliver [All] p2: minsoldermaskwidth=4
PlaneConnect [All] p1: planeconnectstyle=Relief reliefexpansion=10 reliefentries=4 reliefconductorwidth=10 reliefairgap=10
PolygonConnect [All] p1: connectstyle=Direct reliefconductorwidth=10 reliefentries=4 polygonreliefangle="90 Angle" airgapwidth=10
RoomDefinition BGA1 [WithinRoom('BGA1')] p1: confinementstyle=ConfineIn formatcopy=TRUE lockcomponents=FALSE outline 830,2144 1999.28,2144 1999.28,1384.28 1921,1306 1921,1272 1663,1014 1415,1014 1414,1013 1414,840 1477,777 1477,693 1467,683 1435,683 1418,666 1362,666 1362,620 1345,603 1266,603 1256,613 1256,647 1224,679 1190,679 1177,692 1177,733 1084,826 904,826 839,891 839,1037 807,1069 729,1069 711,1051 681,1051 674,1058 674,1151 678,1155 808,1155 844,1191 844,1388 830,1402
RoutingVias ThermalPadVias [IsVia and InAnyComponent] p1: holewidth=7.87 width=19.68 viastyle="Through Hole" minholewidth=5 minwidth=13 maxholewidth=12.99 maxwidth=23.62
RoutingVias [All] p2: holewidth=12.2 width=22.4 viastyle="Through Hole" minholewidth=5.9 minwidth=15.74 maxholewidth=20 maxwidth=40
SMDToCorner [All] p1: distance=25000
SilkToBoardRegionClearance [Not ((IsComment or IsDesignator) And (Hide <> 'False')) and not InRegion(1000,500,4000,800)] p1:
SilkToSilkClearance [All] p1: silktosilkclearance=3
SilkToSolderMaskClearance SilkscreenOverComponentPads [IsPad] p1: minsilkscreentomaskgap=3 clearancetoexposedcopper=TRUE
SolderMaskExpansion [All] p1: expansion=0
Width "Width_1_Diff Pairs" [InNetClass('Diff Pairs')] p1: maxlimit=5.2 minlimit=4 preferedwidth=5.2
Width [All] p2: maxlimit=100 minlimit=4 preferedwidth=6
13 further rules are at their usual default settings.

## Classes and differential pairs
pad class "Mounting Holes PADS": Free-TH1 Free-TH2 Free-TH3 Free-TH4 Free-TH5 Free-TH6 Free-TH7 Free-TH8 Free-TH9
net class "Diff Pairs": NetJ1_28 NetJ1_30 NetJ1_34 NetJ1_36 NetJ1_40 NetJ1_42 NetJ1_46 NetJ1_48 RADAR_LVDS_0M RADAR_LVDS_0P RADAR_LVDS_1M RADAR_LVDS_1P RADAR_LVDS_CLKM RADAR_LVDS_CLKP RADAR_LVDS_FRCLKM RADAR_LVDS_FRCLKP
component class Logo: Logo1 Logo5
component class FiducialMark: FID1 FID2 FID3 FID4 FID5 FID6
component class Label: LBL1
component class PROC073A_Decoupling_caps: C1 C2 C3 C4 C5 C6 C7 C8 C9 C10 C11 C12 C13 C14 C15 C16 C17 C18 C19 C20 C21 C22 C23 C24 C25 C26 C27 C28 C29 C30 C64 L1 L2 L3 L7 R1
component class PROC073A_EVM_Hardware: "CAUTION HOT SURFACE1" FID1 FID2 FID3 FID4 FID5 FID6 LBL1 Logo1 Logo2 LOGO3 Logo4 Logo5 ZZ1 ZZ2 ZZ3 ZZ4
component class PROC073A_HD_Connector_60Pin: J1 J2 R4 R5 R6 R7 R8 R9 R10 R11 R12 R13 R15 R16 R17 R18 R19 R20 R21 R22 R23 R24 R26 R27 R28 R30 R31 R32 R33 R34 R35 R36 R37 R38 R39 R40 R41 R42 R52 R53 R58 R59 R60 R61 R62 R63 R64 R65 R66 R67 R124 R125 R126 R127 R128 R129 R130 R131 R132 R133 R134 R135 R136 R137 R140
component class PROC073A_IWR6843_Chip: C31 C32 C33 R72 R73 R74 R75 R76 R77 R150 R152 R153 R154 R155 R156 R169 TP2 TP3 TP4 TP5 TP6 TP7 U1 Y1
component class PROC073A_PMIC: C37 C38 C39 C40 C41 C42 C43 C44 C45 C46 C47 C48 C49 C50 C51 C52 C53 C54 C55 C56 C60 C61 C62 C66 C67 DS1 L4 L5 L6 Q1 R3 R68 R69 R70 R71 R78 R79 R80 R81 R82 R83 R84 R85 R86 R87 R88 R89 R90 R91 R92 R93 R95 R96 R97 R98 R99 R100 R102 R118 R119 R120 R121 R122 R123 R138 R141 R148 R149 R163 R164 R165 R166 R167 R168 R170 R171 U4 U5 U9
component class PROC073A_QSPI_Flash_section: C34 C35 R43 R44 R45 R46 R47 R48 R49 R50 R51 U2
component class PROC073A_Temp_Current_sensor: C36 C57 C58 C59 C63 C65 R2 R14 R25 R29 R54 R55 R56 R57 R94 R101 R103 R104 R105 R106 R107 R108 R109 R110 R111 R112 R113 R114 R115 R116 R117 R139 R142 R143 R144 R145 R146 R147 R151 R157 R158 R159 R160 R161 R162 U3 U6 U7 U8 U10 U11
net class "TX and RX": RX1 RX2 RX3 RX4 TX1 TX2 TX3
component class AssemblyNote: ZZ1 ZZ2 ZZ3 ZZ4
differential pair NewDifferentialPair8: +NetJ1_30 -NetJ1_28
differential pair NewDifferentialPair7: +NetJ1_36 -NetJ1_34
differential pair NewDifferentialPair6: +NetJ1_42 -NetJ1_40
differential pair NewDifferentialPair5: +NetJ1_48 -NetJ1_46
differential pair NewDifferentialPair4: +RADAR_LVDS_FRCLKM -RADAR_LVDS_FRCLKP
differential pair NewDifferentialPair3: +RADAR_LVDS_CLKM -RADAR_LVDS_CLKP
differential pair NewDifferentialPair2: +RADAR_LVDS_1M -RADAR_LVDS_1P
differential pair NewDifferentialPair1: +RADAR_LVDS_0M -RADAR_LVDS_0P

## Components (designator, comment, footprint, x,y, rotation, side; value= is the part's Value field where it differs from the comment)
C1 "CGA5L1X7R0J226M160AC" 1206_180 1840,835 r180 top value=22uF
C2 "CGA5L1X7R0J226M160AC" 1206_180 610,1650 r0 bottom value=22uF
C3 "CGA5L1X7R0J226M160AC" 1206_180 850,1325 r180 bottom value=22uF
C4 "GCM155R71C224KE02D" 0402L 1374.59,1252 r270 top value=0.22uF
C5 "GCM155R71C224KE02D" 0402L 1419.18,926.41 r180 top value=0.22uF
C6 "GCM155R71C224KE02D" 0402L 1325,985 r180 bottom value=0.22uF
C7 "GCM21BR71A106KE22L" 0805_HV 1495.59,1255 r180 bottom value=10uF
C8 "GCM21BR71A106KE22L" 0805_HV 1495.59,1365 r180 bottom value=10uF
C9 "GCM155R71C224KE02D" 0402L 1200,840 r90 bottom value=0.22uF
C10 "GCM155R71C224KE02D" 0402L 960.59,1045 r180 bottom value=0.22uF
C11 "GCM155R71C224KE02D" 0402L 1007.18,1231.41 r270 bottom value=0.22uF
C12 "GCM155R71C224KE02D" 0402L 1181.59,1204 r180 bottom value=0.22uF
C13 "GCM21BR71A106KE22L" 0805_HV 1183.59,1264 r180 bottom value=10uF
C14 "GCM155R71C224KE02D" 0402L 1505.59,925 r180 top value=0.22uF
C15 "GCM21BR71A106KE22L" 0805_HV 1615,920 r270 top value=10uF
C16 "GCM155R71C224KE02D" 0402L 1163.59,695 r90 top value=0.22uF
C17 "GCM188R70J225KE22D" 0603 800.59,1055 r0 top value=2.2uF
C18 "GCM188R71C105KA64D" 0603 1436.78,851.41 r180 top value=1uF
C19 "GCM155R71C224KE02D" 0402L 1049.18,1231.41 r270 bottom value=0.22uF
C20 "GCM155R71C224KE02D" 0402L 1346.59,1325 r180 bottom value=0.22uF
C21 "GCM155R71C224KE02D" 0402L 806.59,1006 r0 top value=0.22uF
C22 "GCM188R71C105KA64D" 0603 1440.59,995 r180 top value=1uF
C23 "GCM21BR71A106KE22L" 0805_HV 1030.59,1350 r90 bottom value=10uF
C24 "GCM21BR71A106KE22L" 0805_HV 1345.59,1235 r180 bottom value=10uF
C25 "GCM155R71C104KA55D" 0402L 875.59,785 r0 top value=0.1uF
C26 "GCM155R71C104KA55D" 0402L 1134.5,771 r90 top value=0.1uF
C27 "GCM188R70J225KE22D" 0603 810.59,835 r0 top value=2.2uF
C28 "GCM155R71C224KE02D" 0402L 850.59,1140 r0 top value=0.22uF
C29 "GCM155R71C224KE02D" 0402L 980.59,985 r270 bottom value=0.22uF
C30 "GCM155R71E103KA37D" 0402L 1105,795 r270 bottom value=0.01uF
C31 "C0603X7S1A104K030BC" 0201_033 1049.59,892 r90 bottom value=0.1uF
C32 "GJM1555C1H4R7BB01D" 0402L 1435.59,745 r90 top value=4.7pF
C33 "GJM1555C1H4R7BB01D" 0402L 1315.59,650 r180 top value=4.7pF
C34 "CGA2B3X7R1H104K050BB" 0402L 335,1075 r0 top value=0.1uF
C35 "GCM188R71C105KA64D" 0603 335,1175 r270 top value=1uF
C36 "CGA2B3X7R1H104K050BB" 0402L 900,425 r90 bottom value=0.1uF
C37 "CL21B106KOQNNNE" 0805_HV 1385,325 r180 top value=10uF
C38 "0402YC104KAT2A" 0402 1355,210 r180 top value=0.1uF
C39 "0402YC104KAT2A" 0402 633.74,420 r0 top value=0.1uF
C40 "GCM21BD70J226ME36L" 0805 1450,120 r270 top value=22uF
C41 "GCM21BD70J226ME36L" 0805 1535,120 r90 top value=22uF
C42 "CL21B106KOQNNNE" 0805_HV1 843.74,330 r180 top value=10uF
C43 "0402YC104KAT2A" 0402 868.74,225 r0 top value=0.1uF
C44 "GCM21BD70J226ME36L" 0805_HV 498.74,385 r0 top value=22uF
C45 "GCM21BR71A106KE22L" 0805_HV 588.74,80 r0 top value=10uF
C46 "GCM21BD70J226ME36L" 0805 870,95 r180 bottom value=22uF
C47 "GCM21BD70J226ME36L" 0805 838.74,125 r90 top value=22uF
C48 "GRM155R71C103KA01D" 0402 705,205 r270 bottom value=0.01uF
C49 "CL21B106KOQNNNE" 0805_HV1 833.74,445 r90 top value=10uF
C50 "CL10B105KQ8NNNC" 0603 743.74,505 r270 top value=1uF
C51 "GRM188R70J104KA01D" 0603 708.74,815 r90 top value=0.1uF
C52 "GRM155R71C103KA01D" 0402 438.74,250 r270 top value=0.01uF
C53 "0402YC104KAT2A" 0402 1205,165 r0 bottom value=0.1uF
C54 "CGB2A1X6S0J105K033BC" 0402 1355,255 r0 top value=1uF
C55 "CGB2A1X6S0J105K033BC" 0402 633.74,375 r180 top value=1uF
C56 "CGB2A1X6S0J105K033BC" 0402 868.74,270 r180 top value=1uF
C57 "CGA2B3X7R1H104K050BB" 0402L 1560,320 r90 top value=0.1uF
C58 "CGA2B3X7R1H104K050BB" 0402L 635,1430 r90 bottom value=0.1uF
C59 "CGA2B3X7R1H104K050BB" 0402L 830,430 r270 bottom value=0.1uF
C60 "CGA2B3X7S2A102K050BB" 0402 933.74,695 r270 top value=1000pF
C61 "GRM219R61C226ME15L" 0805_HV 1143.74,505 r0 bottom value=22uF
C62 "0402YC104KAT2A" 0402 1060,360 r0 bottom value=0.1uF
C63 "CGA2B3X7R1H104K050BB" 0402L 898.74,888.19 r180 bottom value=0.1uF
C64 "CGA5L1X7R0J226M160AC" 1206_180 510,1585 r270 top value=22uF
C65 "CGA2B3X7R1H104K050BB" 0402L 475,1905 r0 bottom value=0.1uF
C66 "0402YC104KAT2A" 0402 1050,315 r0 bottom value=0.1uF
C67 "0402YC104KAT2A" 0402 1365,740 r270 bottom value=0.1uF
"CAUTION HOT SURFACE1" "CAUTION HOT SURFACE" IEC_HotSurface_Small 603,1849 r0 top
DS1 "TLMY1000-GS08" TLMx1000_Yellow 325,1310 r180 top value=Yellow
FID1 "Fiducial" Fiducial10-20 288.68,1841.73 r90 top
FID2 "Fiducial" Fiducial10-20 323.74,90 r90 bottom
FID3 "Fiducial" Fiducial10-20 1505,100 r90 bottom
FID4 "Fiducial" Fiducial10-20 1895,95 r90 top
FID5 "Fiducial" Fiducial10-20 313,1840 r90 bottom
FID6 "Fiducial" Fiducial10-20 323.74,90 r90 top
J1 "QSH-030-01-L-D-A" Samtec_QSH-030-01-X-D-A 1708.74,580 r0 bottom
J2 "QSH-030-01-L-D-A" Samtec_QSH-030-01-X-D-A 417.24,580 r180 bottom
L1 "BLM18KG121TH1D" 0603 1730,921 r180 top value="120 ohm"
L2 "BLM18KG121TH1D" 0603 835.59,1506 r0 bottom value="120 ohm"
L3 "BLM18KG121TH1D" 0603 835,1410 r0 bottom value="120 ohm"
L4 "DFE252012PD-R47M" DFE252012P 1315,105 r270 top value=470nH
L5 "DFE252012PD-R47M" DFE252012P 943.74,125 r270 top value=470nH
L6 "DFE252012PD-1R0M" DFE252012P 938.74,410 r0 top value=1uH
L7 "BLM18KG121TH1D" 0603 585,1450 r0 top value="120 ohm"
LBL1 "THT-14-423-10" Label_650x200 1251.71,1814.13 r180 bottom
Logo1 "Texas Instruments" TI_Stacked_Overlay_Small 1706.68,490.06 r0 top
Logo2 "CE Mark" CE_Mark_5mm 1453.41,1596.36 r180 bottom
LOGO3 "FCC disclaimer" FCC_disclaimer 951.04,1952.72 r180 bottom (schematic designator Logo3)
Logo4 "WEEE logo" WEEE_Minimum 389,1829 r0 top
Logo5 "Texas Instruments" TI_Symbol_Overlay_Small 1218,1610 r180 bottom
Q1 "BSS123" SOT-23 306,1415 r270 top value=100V
R1 "MCT06030Z0000ZP500" 0603 1355.59,1410 r0 bottom value=0
R2 "CRCW040210K0FKED" 0402L 1728.74,95 r270 bottom value=10.0k
R3 "PMR18EZPFV2L00" 1206 605,555 r90 top value=0.002
R4 "CRCW02010000Z0ED" 0201_Silk 1448.74,395 r180 bottom value=0
R5 "CRCW02010000Z0ED" 0201_Silk 1448.74,290 r0 bottom value=0
R6 "CRCW02010000Z0ED" 0201_Silk 1448.74,360 r180 bottom value=0
R7 "CRCW02010000Z0ED" 0201_Silk 1575,405 r0 top value=0
R8 "CRCW02010000Z0ED" 0201_Silk 1448.74,325 r180 bottom value=0
R9 "CRCW02010000Z0ED" 0201_Silk 1448.74,430 r0 bottom value=0
R10 "CRCW02010000Z0ED" 0201_Silk 1823.74,426.85 r180 top value=0
R11 "CRCW02010000Z0ED" 0201_Silk 1575,440 r0 top value=0
R12 "CRCW02010000Z0ED" 0201_Silk 1575,475 r180 top value=0
R13 "CRCW02010000Z0ED" 0201_Silk 1943.74,445 r0 bottom value=0
R14 "CRCW040210K0FKED" 0402L 1763.74,95 r270 bottom value=10.0k
R15 "CRCW020120R0FNED" 0201_033 1823.74,386.85 r0 top value=20.0
R16 "CRCW02010000Z0ED" 0201_Silk 1945,515 r0 bottom value=0
R17 "CRCW020120R0FNED" 0201_033 1823.74,346.85 r0 top value=20.0
R18 "CRCW020120R0FNED" 0201_033 1575,510 r0 top value=20.0
R19 "CRCW020120R0FNED" 0201_033 1448.74,465 r0 bottom value=20.0
R20 "CRCW020120R0FNED" 0201_033 1448.74,500 r0 bottom value=20.0
R21 "CRCW020120R0FNED" 0201_033 1705,600 r180 top value=20.0
R22 "CRCW02010000Z0ED" 0201_Silk 1823.74,511.85 r180 top value=0
R23 "CRCW020120R0FNED" 0201_033 1610,655 r0 top value=20.0
R24 "CRCW02010000Z0ED" 0201_Silk 1823.74,546.85 r180 top value=0
R25 "CRCW02010000Z0ED" 0201 1875,285 r0 top value=0
R26 "CRCW020120R0FNED" 0201_033 1450,560 r0 bottom value=20.0
R27 "CRCW020120R0FNED" 0201_033 1450,595 r0 bottom value=20.0
R28 "CRCW020120R0FNED" 0201_033 1450,630 r0 bottom value=20.0
R29 "CRCW02010000Z0ED" 0201 1875,250 r0 top value=0
R30 "CRCW02010000Z0ED" 0201_Silk 1823.74,581.85 r180 top value=0
R31 "CRCW02010000Z0ED" 0201_Silk 1943.74,480 r0 bottom value=0
R32 "CRCW02010000Z0ED" 0201_Silk 1823.74,616.85 r180 top value=0
R33 "CRCW02010000Z0ED" 0201_Silk 1823.74,651.85 r180 top value=0
R34 "CRCW02010000Z0ED" 0201_Silk 1475,892 r0 bottom value=0
R35 "CRCW02010000Z0ED" 0201_Silk 1823.74,686.85 r180 top value=0
R36 "CRCW02010000Z0ED" 0201_Silk 1823.74,476.85 r180 top value=0
R37 "CRCW02010000Z0ED" 0201_Silk 1515,926 r0 bottom value=0
R38 "CRCW02010000Z0ED" 0201_Silk 1725,1050 r180 bottom value=0
R39 "CRCW02010000Z0ED" 0201_Silk 1823.74,720 r180 top value=0
R40 "CRCW02010000Z0ED" 0201_Silk 1725,1085 r180 bottom value=0
R41 "CRCW02010000Z0ED" 0201_Silk 1823.74,755 r180 top value=0
R42 "CRCW02010000Z0ED" 0201_Silk 1943.74,410 r180 bottom value=0
R43 "ERJ-2GE0R00X" 0402 390,1190 r90 top value=0
R44 "CRCW040210K0FKED" 0402L 480,715 r90 top value=10.0k
R45 "CRCW020133R2FNED" 0201_Silk 470,1090 r90 top value=33.2
R46 "CRCW020133R2FNED" 0201_Silk 415,725 r90 top value=33.2
R47 "CRCW020133R2FNED" 0201_Silk 518,725 r90 top value=33.2
R48 "CRCW020133R2FNED" 0201_Silk 435,1090 r90 top value=33.2
R49 "CRCW040210K0FKED" 0402L 435,1190 r90 top value=10.0k
R50 "CRCW040247K5FKED" 0402L 355,725 r90 top value=47.5k
R51 "CRCW020133R2FNED" 0201_Silk 395,1090 r90 top value=33.2
R52 "CRCW040210K0FKED" 0402L 820,485 r0 bottom value=10.0k
R53 "CRCW040210K0FKED" 0402L 768.74,580 r90 bottom value=10.0k
R54 "CRCW040210K0FKED" 0402L 943.74,610 r90 bottom value=10.0k
R55 "CRCW02010000Z0ED" 0201 843.74,520 r0 bottom value=0
R56 "CRCW02010000Z0ED" 0201 843.74,565 r0 bottom value=0
R57 "CRCW04020000Z0ED" 0402 940,410 r270 bottom value=0
R58 "CRCW02010000Z0ED" 0201_Silk 1950,715 r270 bottom value=0
R59 "CRCW02010000Z0ED" 0201_Silk 1985,715 r270 bottom value=0
R60 "CRCW02010000Z0ED" 0201_Silk 1450,670 r180 bottom value=0
R61 "CRCW02010000Z0ED" 0201_Silk 1450,705 r180 bottom value=0
R62 "CRCW02010000Z0ED" 0201_Silk 1450,740 r180 bottom value=0
R63 "CRCW02010000Z0ED" 0201_Silk 1450,775 r180 bottom value=0
R64 "CRCW02010000Z0ED" 0201_Silk 1475,858 r180 bottom value=0
R65 "CRCW02010000Z0ED" 0201_Silk 1970,1030 r270 bottom value=0
R66 "CRCW02010000Z0ED" 0201_Silk 1935,1030 r90 bottom value=0
R67 "CRCW02010000Z0ED" 0201_Silk 1900,1030 r90 bottom value=0
R68 "PMR18EZPFV2L00" 1206 450,555 r90 top value=0.002
R69 "CRCW04020000Z0ED" 0402 1305,540 r270 bottom value=0
R70 "PMR18EZPFV2L00" 1206 1720.83,90 r0 top value=0.002
R71 "PMR18EZPFV2L00" 1206 495,1265 r180 bottom value=0.002
R72 "ERJ-2GE0R00X" 0402 800.59,1420 r0 top value=0
R73 "ERJ-2GE0R00X" 0402 800.59,1375 r0 top value=0
R74 "ERJ-2GE0R00X" 0402 800.59,1285 r0 top value=0
R75 "ERJ-2GE0R00X" 0402 800.59,1330 r0 top value=0
R76 "ERJ-2GE0R00X" 0402 1490,740 r90 top value=0
R77 "ERJ-2GE0R00X" 0402 1268.74,600 r180 top value=0
R78 "ERJ-2GEJ511X" 0402L 430,1295 r270 top value=510
R79 "ERJ-2GEJ511X" 0402L 305,1585 r270 bottom value=510
R80 "CRCW0402100KFKED" 0402L 270,1585 r90 bottom value=100k
R81 "PMR18EZPFV2L00" 1206 730,205 r90 top value=0.002
R82 "CRCW04020000Z0ED" 0402 1223.74,470 r0 top value=0
R83 "CRCW04020000Z0ED" 0402 705,100 r270 bottom value=0
R84 "CRCW04020000Z0ED" 0402 1113.74,470 r180 top value=0
R85 "CRCW040212K1FKED" 0402 388.74,250 r90 top value=12.1k
R86 "CRCW040210K0JNED" 0402 1355,265 r0 bottom value=10k
R87 "CRCW040210K0JNED" 0402 929,515 r90 top value=10k
R88 "CRCW02010000Z0ED" 0201 1048.74,40 r0 top value=0
R89 "CRCW02010000Z0ED" 0201 1048.74,75 r0 top value=0
R90 "CRCW04020000Z0ED" 0402 1220,240 r270 bottom value=0
R91 "CRCW04020000Z0ED" 0402 1020,240 r270 bottom value=0
R92 "CRCW040248K7FKED" 0402 438.74,145 r90 top value=48.7k
R93 "CRCW04020000Z0ED" 0402 1208.23,344.49 r270 bottom value=0
R94 "CRCW040210K0FKED" 0402L 1880,215 r180 top value=10.0k
R95 "CRCW040210K0JNED" 0402 1315,165 r180 bottom value=10k
R96 "PMR18EZPFV2L00" 1206 895,195 r180 bottom value=0.002
R97 "CRCW040211K8FKED" 0402 1158.74,345 r90 bottom value=11.8k
R98 "CRCW04020000Z0ED" 0402 1005,520 r270 top value=0
R99 "MCT06030Z0000ZP500" 0603 1025,640 r180 bottom value=0
R100 "CRCW040210K0JNED" 0402 1060,160 r0 bottom value=10k
R101 "CRCW040210K0FKED" 0402L 1698.74,95 r90 bottom value=10.0k
R102 "CRCW04020000Z0ED" 0402 1312,60 r180 bottom value=0
R103 "CRCW040210K0FKED" 0402L 1798.74,95 r90 bottom value=10.0k
R104 "CRCW040210K0FKED" 0402L 360,1480 r90 bottom value=10.0k
R105 "CRCW040210K0FKED" 0402L 325,1480 r90 bottom value=10.0k
R106 "CRCW040210K0FKED" 0402L 595,80 r270 bottom value=10.0k
R107 "CRCW040210K0FKED" 0402L 630,85 r270 bottom value=10.0k
R108 "CRCW02010000Z0ED" 0201 450,1525 r90 bottom value=0
R109 "CRCW02010000Z0ED" 0201 715,490 r0 bottom value=0
R110 "CRCW02010000Z0ED" 0201 485,1525 r90 bottom value=0
R111 "CRCW02010000Z0ED" 0201 715,455 r0 bottom value=0
R112 "CRCW040210K0FKED" 0402L 415,1385 r270 top value=10.0k
R113 "CRCW040210K0FKED" 0402L 375,1580 r270 top value=10.0k
R114 "CRCW040210K0FKED" 0402L 275,1580 r270 top value=10.0k
R115 "CRCW040210K0FKED" 0402L 635,460 r270 bottom value=10.0k
R116 "CRCW040210K0FKED" 0402L 555,80 r90 bottom value=10.0k
R117 "CRCW040210K0FKED" 0402L 615,160 r270 bottom value=10.0k
R118 "CRCW040210K0JNED" 0402 1065,60 r0 bottom value=10k
R119 "CRCW0402510RJNED" 0402 738.74,675 r270 bottom value=510
R120 "ERJ-2RKF1003X" 0402 848.74,610 r0 bottom value=100k
R121 "CRCW04020000Z0ED" 0402 1003.74,520 r270 bottom value=0
R122 "RC0603JR-071KL" 0603 1290,378 r90 bottom value=1.0k
R123 "PMR18EZPFV2L00" 1206 903.74,740 r0 bottom value=0.002
R124 "CRCW020120R0FNED" 0201_033 658.74,800 r180 bottom value=20.0
R125 "CRCW020120R0FNED" 0201_033 658.74,765 r180 bottom value=20.0
R126 "CRCW020120R0FNED" 0201_033 643.74,730 r180 bottom value=20.0
R127 "CRCW020120R0FNED" 0201_033 643.74,695 r180 bottom value=20.0
R128 "CRCW020120R0FNED" 0201_033 643.74,660 r180 bottom value=20.0
R129 "CRCW020120R0FNED" 0201_033 643.74,630 r180 bottom value=20.0
R130 "CRCW020120R0FNED" 0201_033 643.74,595 r180 bottom value=20.0
R131 "CRCW02010000Z0ED" 0201_Silk 285,580 r0 top value=0
R132 "CRCW020120R0FNED" 0201_033 643.74,560 r180 bottom value=20.0
R133 "CRCW02010000Z0ED" 0201_Silk 285,615 r0 top value=0
R134 "CRCW02010000Z0ED" 0201_Silk 285,545 r0 top value=0
R135 "CRCW02010000Z0ED" 0201_Silk 285,510 r0 top value=0
R136 "CRCW02010000Z0ED" 0201_Silk 285,475 r0 top value=0
R137 "CRCW02010000Z0ED" 0201_Silk 285,440 r0 top value=0
R138 "RCS06030000Z0EA" 0603 738.74,660 r90 top value=0
R139 "CRCW040210K0FKED" 0402L 960,1195 r90 bottom value=10.0k
R140 "CRCW02010000Z0ED" 0201_Silk 658.74,835 r180 bottom value=0
R141 "CRCW040210K0JNED" 0402 1170,60 r180 bottom value=10k
R142 "CRCW040210K0FKED" 0402L 965,1115 r0 bottom value=10.0k
R143 "CRCW02010000Z0ED" 0201 888.74,1195 r90 bottom value=0
R144 "CRCW02010000Z0ED" 0201 833.74,1195 r90 bottom value=0
R145 "CRCW040210K0FKED" 0402L 798.74,1195 r270 bottom value=10.0k
R146 "CRCW040210K0FKED" 0402L 925,1195 r270 bottom value=10.0k
R147 "CRCW040210K0FKED" 0402L 965,1080 r180 bottom value=10.0k
R148 "CRCW040210K0JNED" 0402 423.74,50 r0 bottom value=10k
R149 "CRCW02010000Z0ED" 0201 413.74,120 r180 bottom value=0
R150 "CRCW040210K0JNED" 0402 1950,715 r90 top value=10k
R151 "CRCW04020000Z0ED" 0402 985,410 r270 bottom value=0
R152 "CRCW040210K0FKED" 0402L 1940,410 r180 top value=10.0k
R153 "CRCW0402100KFKED" 0402L 1840,1080 r0 bottom value=100k
R154 "CRCW0402100KFKED" 0402L 1840,1045 r0 bottom value=100k
R155 "CRCW0402100KFKED" 0402L 1945,455 r180 top value=100k
R156 "CRCW0402100KFKED" 0402L 1230,755 r90 bottom value=100k
R157 "CRCW040210K0FKED" 0402L 475,1835 r180 bottom value=10.0k
R158 "CRCW040210K0FKED" 0402L 475,1865 r0 bottom value=10.0k
R159 "CRCW02010000Z0ED" 0201 465,1720 r270 bottom value=0
R160 "CRCW02010000Z0ED" 0201 500,1720 r270 bottom value=0
R161 "CRCW040210K0FKED" 0402L 870,1795 r0 bottom value=10.0k
R162 "CRCW040210K0FKED" 0402L 870,1760 r180 bottom value=10.0k
R163 "CRCW040210K0JNED" 0402 638.7,249.69 r90 bottom value=10k
R164 "CRCW040210K0JNED" 0402 530,505 r90 top value=10k
R165 "CRCW04020000Z0ED" 0402 1120,600 r270 bottom value=0
R166 "CRCW04020000Z0ED" 0402 1315,740 r270 bottom value=0
R167 "CRCW04020000Z0ED" 0402 1126,270 r180 bottom value=0
R168 "CRCW04020000Z0ED" 0402 1315,115 r0 bottom value=0
R169 "CRCW040210K0JNED" 0402 1900,970 r180 top value=10k
R170 "CRCW040210K0JNED" 0402 1215,610 r0 bottom value=10k
R171 "CRCW04020000Z0ED" 0402 1245,520 r90 bottom value=0
TP2 "TP_SM_1MM" TP_SM_1MM 385,345 r90 top
TP3 "TP_SM_1MM" TP_SM_1MM 545,1345 r90 top
TP4 "TP_SM_1MM" TP_SM_1MM 532,1277 r90 top
TP5 "TP_SM_1MM" TP_SM_1MM 691,1325 r90 top
TP6 "TP_SM_1MM" TP_SM_1MM 1552,760 r90 top
TP7 "TP_SM_1MM" TP_SM_1MM 1450,665 r90 top
U1 "IWR6843QAGABL" ABL0161B 1125.98,1059.62 r270 top
U2 "MX25V1635FZNQ" WSON-8L_6x5MM_EP 434,900 r90 top
U3 "TMP112AQDRLRQ1" DRL0006A 923.74,520 r270 bottom
U4 "LP87702DRHBRQ1" RHB0032N 1113.74,250 r270 top
U5 "TPS7A5301QRGRRQ1" RGR0020A 573.74,230 r0 top
U6 "INA226AIDGST" DGS0010A_L 1703.74,275 r180 top
U7 "INA226AIDGST" DGS0010A_L 495,1390 r0 bottom
U8 "INA226AIDGST" DGS0010A_L 795,325 r0 bottom
U9 "TPS22917DBVR" DBV0006A_N 838.74,660 r90 top
U10 "INA226AIDGST" DGS0010A_L 810.59,1020 r270 bottom
U11 "CAT24C08WI-GT3" SOIC-8 675,1820 r180 bottom
Y1 "CX3225SA40000D0PTWCC" Kyocera_CX3225SA 1335.59,735 r90 top
ZZ1 "This Assembly Note is for PCB labels only" AssemblyNoteLabel -833.57,3067.5 r0 top
ZZ2 "These assemblies are ESD sensitive, ESD precautions shall be observed." AssemblyNote -831.16,2990.34 r0 top
ZZ3 "These assemblies must be clean and free from flux and all contaminants. Use of no clean flux is not acceptable." AssemblyNote -831.16,2903.53 r0 top
ZZ4 "These assemblies must comply with workmanship standards IPC-A-610 Class 2, unless otherwise specified." AssemblyNote -835.98,2811.9 r0 top

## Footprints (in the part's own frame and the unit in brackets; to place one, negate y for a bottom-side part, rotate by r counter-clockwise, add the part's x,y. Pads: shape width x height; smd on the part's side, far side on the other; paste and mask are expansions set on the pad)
0201 [mm] "Data from Kemet datasheet CC101_COM dated 7/28/11"
  rect 0.46x0.42 smd mask+0: 1(-0.33,0) 2(0.33,0)
  body extent -0.31,-0.16 0.31,0.16, height 0.26
0201_033 [mm] "SMD, 2-Leads, Height 0.33mm"
  rect 0.46x0.42 smd mask+0: 1(-0.33,0) 2(0.33,0)
  body extent -0.31,-0.16 0.31,0.16, height 0.33
0201_Silk [mm] "Data from Kemet datasheet CC101_COM dated 7/28/11"
  rect 0.46x0.42 smd mask+0: 1(-0.33,0) 2(0.33,0)
  silkscreen extent -0.75,-0.4 0.75,0.4, body extent -0.31,-0.16 0.31,0.16, height 0.26
0402 [mm] "0402 from SM-752 data"
  rect 0.8x0.6 smd: 1(-0.6,0) 2(0.6,0)
  silkscreen extent -1.22,-0.52 1.22,0.52, body extent -0.55,-0.3 0.55,0.3, height 0.6
0402L [mm] "0402 from SM-752 data"
  rect 0.6x0.5 smd: 1(-0.5,0) 2(0.5,0)
  body extent -0.55,-0.3 0.55,0.3, height 0.6
0603 [mm] "0603 from SM-752 data"
  rect 1x0.95 smd: 1(-0.8,0) 2(0.8,0)
  silkscreen extent -1.52,-0.69 1.52,0.69, body extent -0.87,-0.47 0.87,0.47, height 1
0805 [mm] "0805 from SM-752 data"
  rect 1.3x1.5 smd: 1(-0.85,0) 2(0.85,0)
  silkscreen extent -1.72,-0.97 1.72,0.97, body extent -1.1,-0.72 1.1,0.72, height 1.45
0805_HV [mil] "0805 with 30mil clearance between pads"
  rect 50x63 smd: 1(-40,0) 2(40,0)
  silkscreen extent -74,-40 74,40, body extent -43,-29 43,29, height 57
0805_HV1 [mm] "Custom footprint based on analyzing multiple manufacturer recommendations"
  rrect10% 1x1.25 smd: 1(-1,0) 2(1,0)
  silkscreen extent -0.2,-0.75 0.2,0.75, body extent -1.1,-0.72 1.1,0.73, height 1.45
1206 [mm] "1206 from SM-752 data"
  rect 1.3x1.85 smd: 1(-1.45,0) 2(1.45,0)
  silkscreen extent -2.4,-1.21 2.4,1.21, body extent -1.7,-0.9 1.7,0.9, height 1.35
1206_180 [mm] "1206_180"
  rect 1.1x1.6 smd: 1(-1.7,0) 2(1.7,0)
  silkscreen extent -0.9,-1 0.9,1, body extent -1.75,-0.95 1.75,0.95, height 1.8
ABL0161B [mm] "BGA, 161-Balls, Body 10.4x10.4mm, Pitch 0.65mm"
  round 0.32 smd: A1(-4.55,4.55) A2(-3.9,4.55) A3(-3.25,4.55) A5(-1.95,4.55) A7(-0.65,4.55) A9(0.65,4.55) A10(1.3,4.55) A13(3.25,4.55) A14(3.9,4.55) A15(4.55,4.55) B1(-4.55,3.9) B2(-3.9,3.9) B3(-3.25,3.9) B4(-2.6,3.9) B5(-1.95,3.9) B6(-1.3,3.9) B7(-0.65,3.9) B8(0,3.9) B9(0.65,3.9) B10(1.3,3.9) B11(1.95,3.9) B12(2.6,3.9) B13(3.25,3.9) B14(3.9,3.9) B15(4.55,3.9) C1(-4.55,3.25) C2(-3.9,3.25) C3(-3.25,3.25) C4(-2.6,3.25) C5(-1.95,3.25) C6(-1.3,3.25) C7(-0.65,3.25) C8(0,3.25) C9(0.65,3.25) C13(3.25,3.25) C14(3.9,3.25) C15(4.55,3.25) D2(-3.9,2.6) D13(3.25,2.6) D14(3.9,2.6) D15(4.55,2.6) E1(-4.55,1.95) E2(-3.9,1.95) E3(-3.25,1.95) E5(-1.95,1.95) E6(-1.3,1.95) E8(0,1.95) E10(1.3,1.95) E11(1.95,1.95) E13(3.25,1.95) E14(3.9,1.95) E15(4.55,1.95) F2(-3.9,1.3) F3(-3.25,1.3) F5(-1.95,1.3) F9(0.65,1.3) F11(1.95,1.3) F13(3.25,1.3) F14(3.9,1.3) F15(4.55,1.3) G1(-4.55,0.65) G2(-3.9,0.65) G3(-3.25,0.65) G5(-1.95,0.65) G6(-1.3,0.65) G7(-0.65,0.65) G8(0,0.65) G10(1.3,0.65) G13(3.25,0.65) G14(3.9,0.65) G15(4.55,0.65) H2(-3.9,0) H3(-3.25,0) H5(-1.95,0) H7(-0.65,0) H9(0.65,0) H11(1.95,0) H13(3.25,0) H14(3.9,0) H15(4.55,0) J1(-4.55,-0.65) J2(-3.9,-0.65) J3(-3.25,-0.65) J5(-1.95,-0.65) J6(-1.3,-0.65) J7(-0.65,-0.65) J8(0,-0.65) J10(1.3,-0.65) J13(3.25,-0.65) J14(3.9,-0.65) J15(4.55,-0.65) K2(-3.9,-1.3) K3(-3.25,-1.3) K5(-1.95,-1.3) K7(-0.65,-1.3) K8(0,-1.3) K9(0.65,-1.3) K10(1.3,-1.3) K11(1.95,-1.3) K13(3.25,-1.3) K14(3.9,-1.3) K15(4.55,-1.3) L1(-4.55,-1.95) L2(-3.9,-1.95) L3(-3.25,-1.95) L5(-1.95,-1.95) L6(-1.3,-1.95) L8(0,-1.95) L10(1.3,-1.95) L13(3.25,-1.95) L14(3.9,-1.95) L15(4.55,-1.95) M2(-3.9,-2.6) M3(-3.25,-2.6) M14(3.9,-2.6) M15(4.55,-2.6) N1(-4.55,-3.25) N2(-3.9,-3.25) N3(-3.25,-3.25) N4(-2.6,-3.25) N5(-1.95,-3.25) N6(-1.3,-3.25) N7(-0.65,-3.25) N8(0,-3.25) N9(0.65,-3.25) N10(1.3,-3.25) N11(1.95,-3.25) N12(2.6,-3.25) N13(3.25,-3.25) N14(3.9,-3.25) N15(4.55,-3.25) P1(-4.55,-3.9) P2(-3.9,-3.9) P3(-3.25,-3.9) P4(-2.6,-3.9) P5(-1.95,-3.9) P6(-1.3,-3.9) P7(-0.65,-3.9) P8(0,-3.9) P9(0.65,-3.9) P10(1.3,-3.9) P11(1.95,-3.9) P12(2.6,-3.9) P13(3.25,-3.9) P14(3.9,-3.9) P15(4.55,-3.9) R1(-4.55,-4.55) R2(-3.9,-4.55) R3(-3.25,-4.55) R4(-2.6,-4.55) R5(-1.95,-4.55) R6(-1.3,-4.55) R7(-0.65,-4.55) R8(0,-4.55) R9(0.65,-4.55) R10(1.3,-4.55) R11(1.95,-4.55) R12(2.6,-4.55) R13(3.25,-4.55) R14(3.9,-4.55) R15(4.55,-4.55)
  silkscreen extent -5.3,-5.3 5.3,5.3, body extent -5.2,-5.2 5.2,5.2, height 0.62
AssemblyNote [mil] "Assembly Note"
AssemblyNoteLabel [mil] "Assembly Note for PCB Labels"
CE_Mark_5mm [mil] "Minimum text height for CE Mark"
  silkscreen extent -138,-98 138,98
DBV0006A_N [mm] "SOT23, 6-Leads, Body 2.9x1.6mm, Pitch 0.95mm, Lead Span 2.8mm, IPC Medium Density"
  rrect17% 1x0.6 smd: 1(-1.375,0.95) 2(-1.375,0) 3(-1.375,-0.95) 4(1.375,-0.95) 5(1.375,0) 6(1.375,0.95)
  silkscreen extent -1.68,-1.55 0.5,1.55, body extent -1.42,-1.46 1.42,1.46, height 1.12
DFE252012P [mm] "TOKO, Pad sizes increased as per request"
  rect 0.9x2 smd: 1(-1.05,0) 2(1.05,0)
  silkscreen extent -0.3,-1.2 0.3,1.2, body extent -1.35,-1.1 1.35,1.1, height 1.2
DGS0010A_L [mm] "TSSOP, 10-Leads, Body 3x3mm, Pitch 0.5mm, IPC High Density"
  oval 1.15x0.25 smd: 1(-2.125,1) 2(-2.125,0.5) 3(-2.125,0) 4(-2.125,-0.5) 5(-2.125,-1) 6(2.125,-1) 7(2.125,-0.5) 8(2.125,0) 9(2.125,0.5) 10(2.125,1)
  silkscreen extent -2.65,-1.55 0.9,1.55, body extent -2.45,-1.5 2.45,1.5, height 0.96
DRL0006A [mm] "SOTFL, 6-Flat Leads, Body 1.2x1.6x0.6mm, Pitch 0.5mm, TI recommended"
  rrect33% 0.67x0.3 smd: 1(-0.74,0.5) 2(-0.74,0) 3(-0.74,-0.5) 4(0.74,-0.5) 5(0.74,0) 6(0.74,0.5)
  silkscreen extent -0.9,-0.95 0.5,0.95, body extent -0.8,-0.8 0.8,0.8, height 0.61
FCC_disclaimer [mil]
Fiducial10-20 [mm]
  round 1 smd mask+0.5: 1(0,0)
  Top Layer keep-out circle w1.178: c0,0 r0.5
IEC_HotSurface_Small [mil]
  silkscreen extent -107,-93 107,92
Kyocera_CX3225SA [mm] "SMD, 4-Leads, Body 3.2x2.5mm"
  rrect10% 1.05x1.45 smd: 1(-0.925,1.075) 2(-0.925,-1.075) 3(0.925,-1.075) 4(0.925,1.075)
  silkscreen extent -1,2.28 -0.87,2.4, body extent -1.3,-1.65 1.3,1.65, height 0.9
Label_650x200 [mil] "Thermal Transfer Label"
  round 1 on Mech14: 0(0,0)
  silkscreen extent -325,-100 325,100, body extent -325,-100 325,100, height 1
RGR0020A [mm] "QFN, 20-Leads, Body 3.5x3.5mm, Pitch 0.5mm, Thermal Pad 2.05x2.05mm, TI Recommended"
  rrect42% 0.6x0.24 smd: 1(-1.65,1) 2(-1.65,0.5) 3(-1.65,0) 4(-1.65,-0.5) 5(-1.65,-1) 11(1.65,-1) 12(1.65,-0.5) 13(1.65,0) 14(1.65,0.5) 15(1.65,1)
  rrect42% 0.24x0.6 smd: 6(-1,-1.65) 7(-0.5,-1.65) 8(0,-1.65) 9(0.5,-1.65) 10(1,-1.65) 16(1,1.65) 17(0.5,1.65) 18(0,1.65) 19(-0.5,1.65) 20(-1,1.65)
  rrect5% 2.05x2.05 smd paste-1.025: 21(0,0)
  silkscreen extent -1.97,-1.97 1.97,1.97, body extent -1.75,-1.75 1.75,1.75, height 1
RHB0032N [mm] "QFN, 32-Leads, Body 5x5mm, Pitch 0.5mm, Thermal Pad 3.45x3.45mm"
  rrect40% 0.6x0.25 smd: 1(-2.4,1.75) 2(-2.4,1.25) 3(-2.4,0.75) 4(-2.4,0.25) 5(-2.4,-0.25) 6(-2.4,-0.75) 7(-2.4,-1.25) 8(-2.4,-1.75) 17(2.4,-1.75) 18(2.4,-1.25) 19(2.4,-0.75) 20(2.4,-0.25) 21(2.4,0.25) 22(2.4,0.75) 23(2.4,1.25) 24(2.4,1.75)
  rrect40% 0.25x0.6 smd: 9(-1.75,-2.4) 10(-1.25,-2.4) 11(-0.75,-2.4) 12(-0.25,-2.4) 13(0.25,-2.4) 14(0.75,-2.4) 15(1.25,-2.4) 16(1.75,-2.4) 25(1.75,2.4) 26(1.25,2.4) 27(0.75,2.4) 28(0.25,2.4) 29(-0.25,2.4) 30(-0.75,2.4) 31(-1.25,2.4) 32(-1.75,2.4)
  rrect3% 3.45x3.45 smd paste-1.725: 33(0,0)
  rrect7% 1.49x1.49 on Top Paste: ""(-0.845,0.845) ""(-0.845,-0.845) ""(0.845,0.845) ""(0.845,-0.845)
  silkscreen extent -2.72,-2.73 2.72,2.73, body extent -2.5,-2.5 2.5,2.5, height 0.9
Samtec_QSH-030-01-X-D-A [mm] "Receptacle, 0.5 mm, 30x2, TH"
  rect 2.27x0.279 smd: 1(-2.865,7.25) 2(2.865,7.25) 3(-2.865,6.75) 4(2.865,6.75) 5(-2.865,6.25) 6(2.865,6.25) 7(-2.865,5.75) 8(2.865,5.75) 9(-2.865,5.25) 10(2.865,5.25) 11(-2.865,4.75) 12(2.865,4.75) 13(-2.865,4.25) 14(2.865,4.25) 15(-2.865,3.75) 16(2.865,3.75) 17(-2.865,3.25) 18(2.865,3.25) 19(-2.865,2.75) 20(2.865,2.75) 21(-2.865,2.25) 22(2.865,2.25) 23(-2.865,1.75) 24(2.865,1.75) 25(-2.865,1.25) 26(2.865,1.25) 27(-2.865,0.75) 28(2.865,0.75) 29(-2.865,0.25) 30(2.865,0.25) 31(-2.865,-0.25) 32(2.865,-0.25) 33(-2.865,-0.75) 34(2.865,-0.75) 35(-2.865,-1.25) 36(2.865,-1.25) 37(-2.865,-1.75) 38(2.865,-1.75) 39(-2.865,-2.25) 40(2.865,-2.25) 41(-2.865,-2.75) 42(2.865,-2.75) 43(-2.865,-3.25) 44(2.865,-3.25) 45(-2.865,-3.75) 46(2.865,-3.75) 47(-2.865,-4.25) 48(2.865,-4.25) 49(-2.865,-4.75) 50(2.865,-4.75) 51(-2.865,-5.25) 52(2.865,-5.25) 53(-2.865,-5.75) 54(2.865,-5.75) 55(-2.865,-6.25) 56(2.865,-6.25) 57(-2.865,-6.75) 58(2.865,-6.75) 59(-2.865,-7.25) 60(2.865,-7.25)
  round 0 hole 1.02 unplated mask+0.127: MH1(2.67,10.065) MH2(2.67,-10.065)
  rect 0.43x2.54 smd: MP1(0,8.065) MP4(0,-8.065)
  rect 0.43x4.7 smd: MP2(0,3.175) MP3(0,-3.175)
  silkscreen extent -3.9,-10.66 3.62,10.66, body extent -3.75,-10.64 3.75,10.67, height 3.25
SOIC-8 [mm] "duplicate of SO-8.  SOIC, 8-Leads, Body 5.0x4.0mm (max), Pitch 1.27mm, IPC Medium Density"
  rrect17% 1.45x0.6 smd: 1(-2.725,1.905) 2(-2.725,0.635) 3(-2.725,-0.635) 4(-2.725,-1.905) 5(2.725,-1.905) 6(2.725,-0.635) 7(2.725,0.635) 8(2.725,1.905)
  silkscreen extent -3.5,-2.5 0.9,2.5, body extent -3,-2.45 3,2.45, height 1.63
SOT-23 [mm] "SOT23, 3-Leads, Body 2.9x1.3mm, Pitch 0.95mm, Lead Span 2.5mm, IPC Medium Density"
  rrect50% 1x0.6 smd: 1(-1.2,0.95) 2(-1.2,-0.95) 3(1.2,0)
  silkscreen extent -1.63,-1.5 0.7,1.5, body extent -1.16,-1.45 1.21,1.45, height 1
TI_Stacked_Overlay_Small [mil]
  silkscreen extent -418,-78 -237,98
TI_Symbol_Overlay_Small [mil]
  silkscreen extent -90,-88 91,88
TLMx1000_Yellow [mm] "SMD, 2-Leads, Body 1.6x0.8mm"
  rrect17% 0.6x0.8 smd: 1(-0.725,0) 2(0.725,0)
  silkscreen extent -0.97,-0.8 1.6,0.8, body extent -0.85,-0.45 0.85,0.45, height 0.65
TP_SM_1MM [mm] "1mm Test Point, SMT"
  round 1 smd paste-0.5: 1(0,0)
WEEE_Minimum [mil] "WEEElie bin"
  silkscreen extent -95,-172 99,104
WSON-8L_6x5MM_EP [mm] "SMD, 8-Leads, Body 6x5mm, Pitch 1.27mm"
  rrect25% 0.8x0.4 smd: 1(-2.8,1.905) 2(-2.8,0.635) 3(-2.8,-0.635) 4(-2.8,-1.905) 5(2.8,-1.905) 6(2.8,-0.635) 7(2.8,0.635) 8(2.8,1.905)
  rrect3% 3.4x4 smd paste-3: 9(0,0)
  rrect7% 1.468x1.698 on Top Paste: ""(-0.834,-0.949) ""(-0.834,0.949) ""(0.834,-0.949) ""(0.834,0.949)
  silkscreen extent -3.2,-2.7 3.2,2.7, body extent -3.05,-2.55 3.05,2.55, height 0.8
